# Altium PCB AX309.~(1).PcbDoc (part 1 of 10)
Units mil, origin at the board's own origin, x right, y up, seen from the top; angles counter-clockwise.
Board outline 5185 x 3614 mil, 4 copper layers (Top Layer, GND, Mid-Layer 1, Bottom Layer); 191 components, 352 nets, 1106 pads, 425 vias.
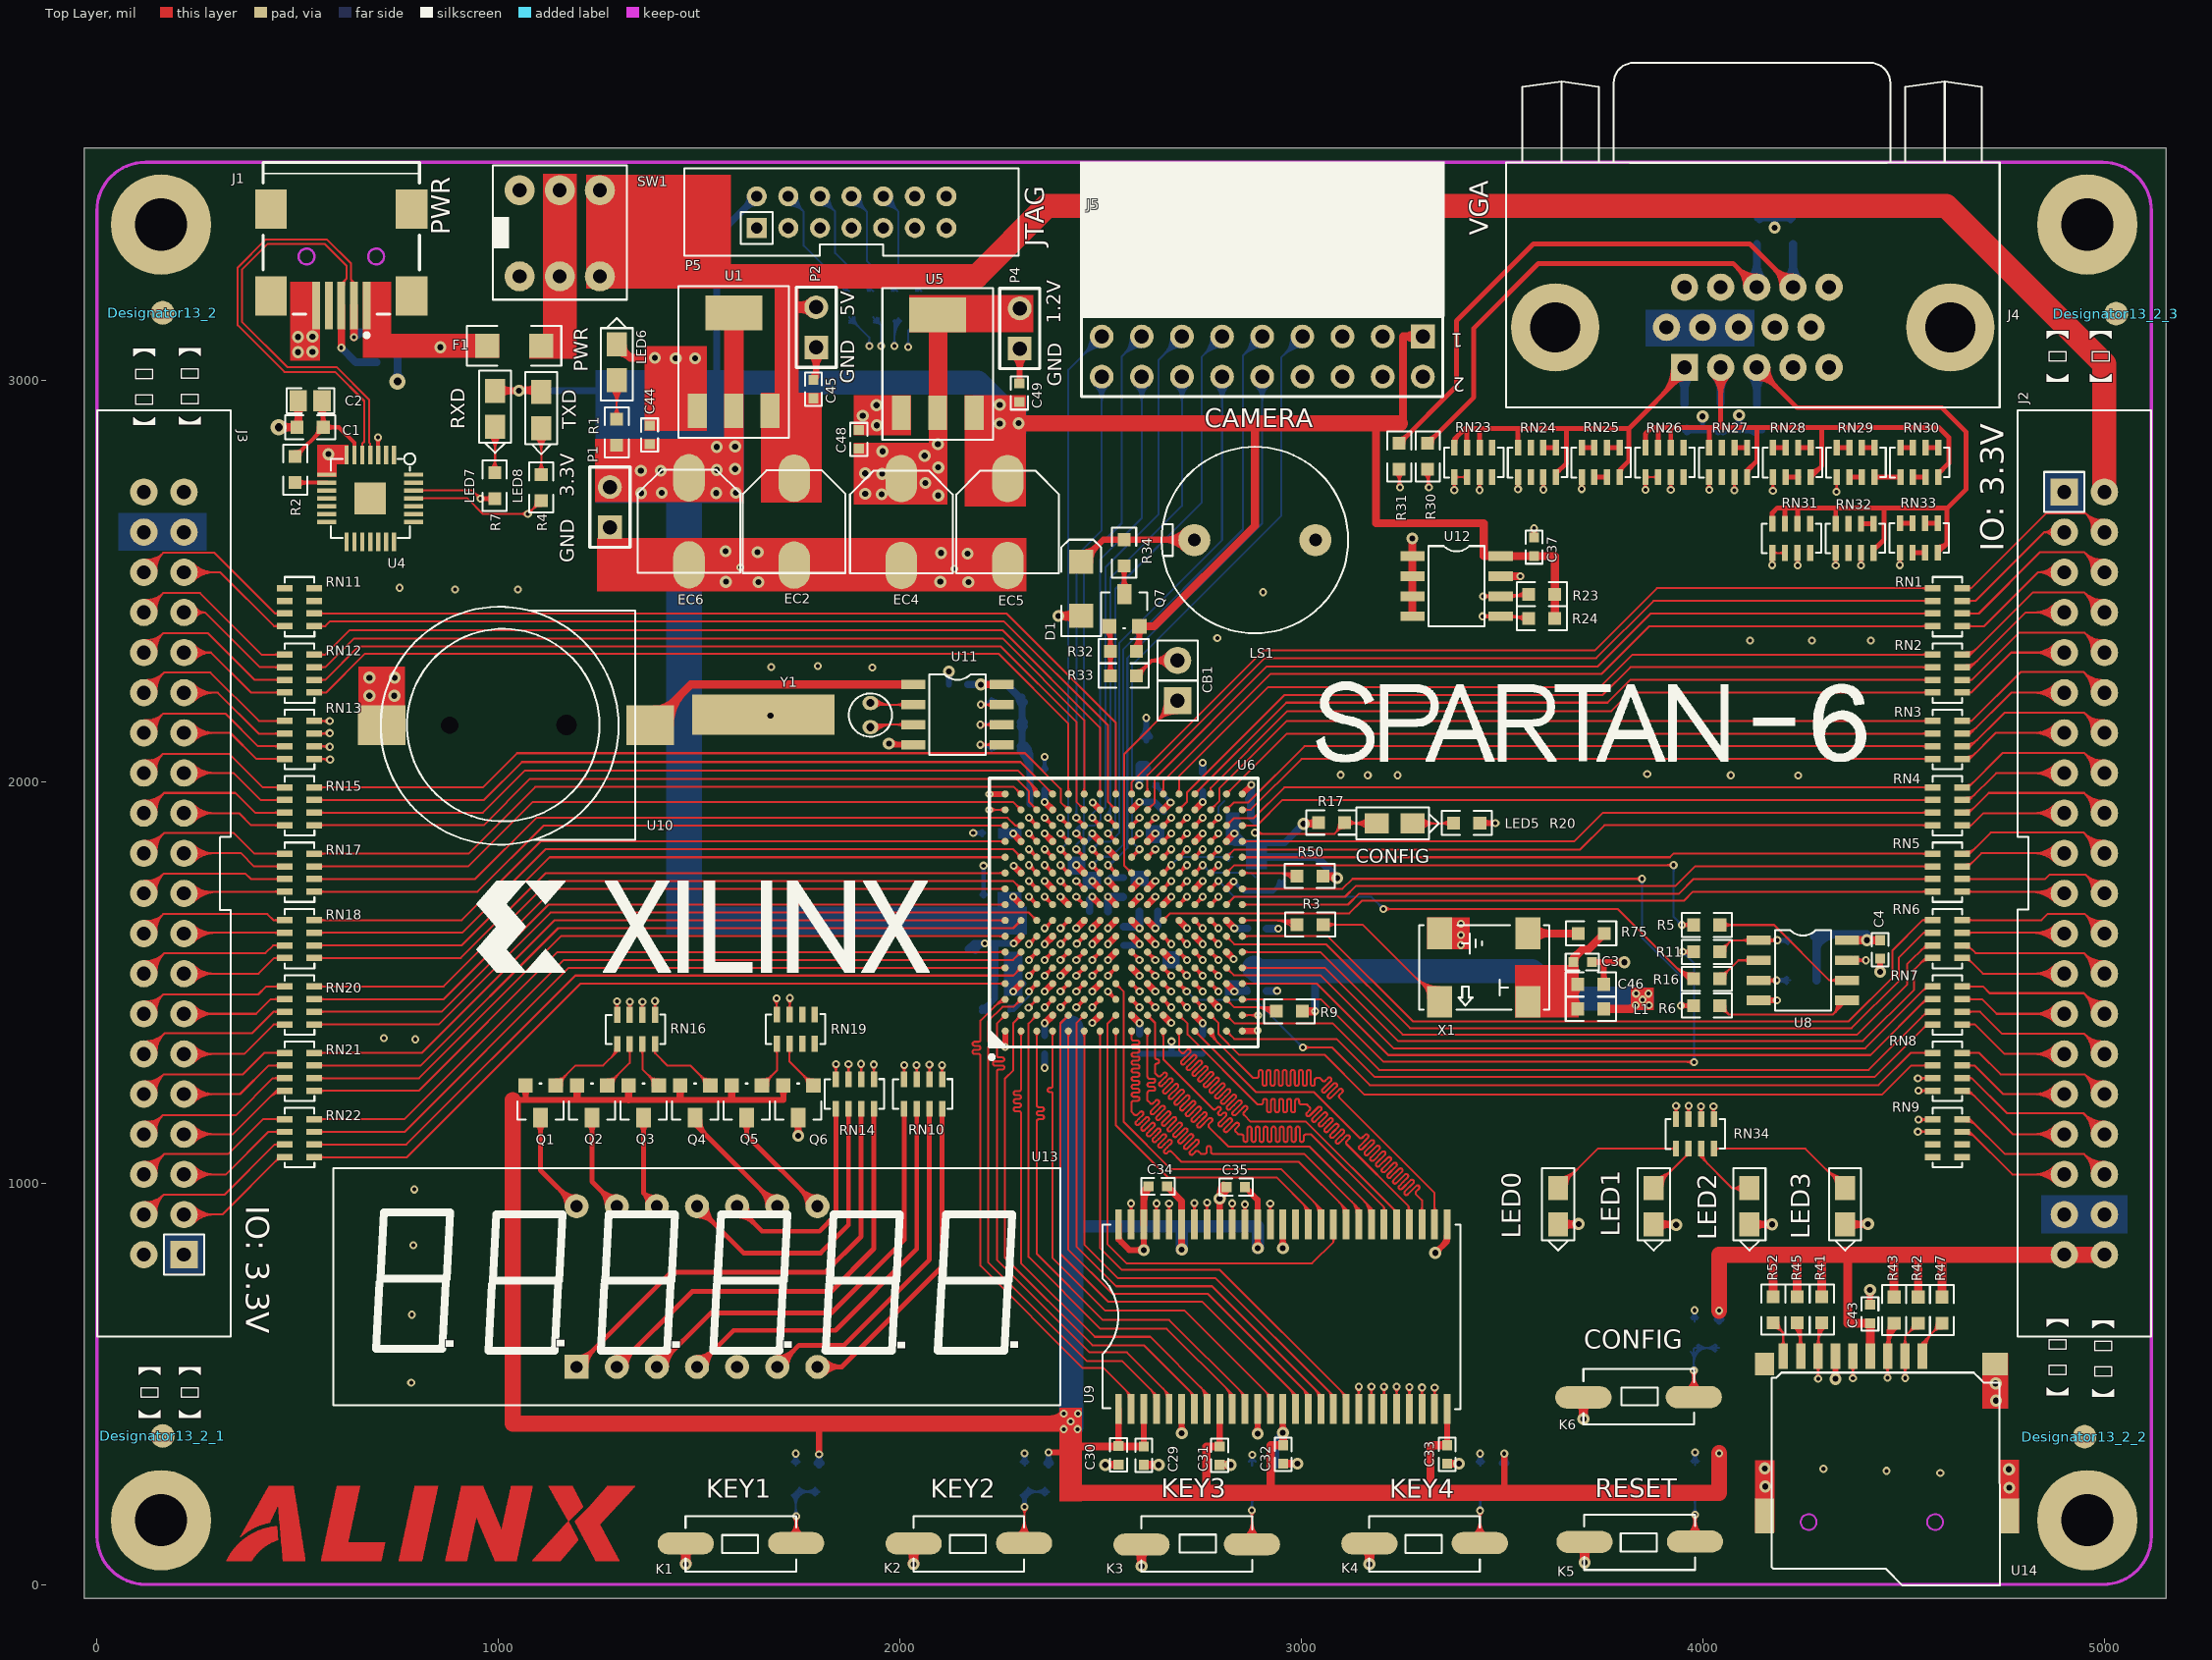
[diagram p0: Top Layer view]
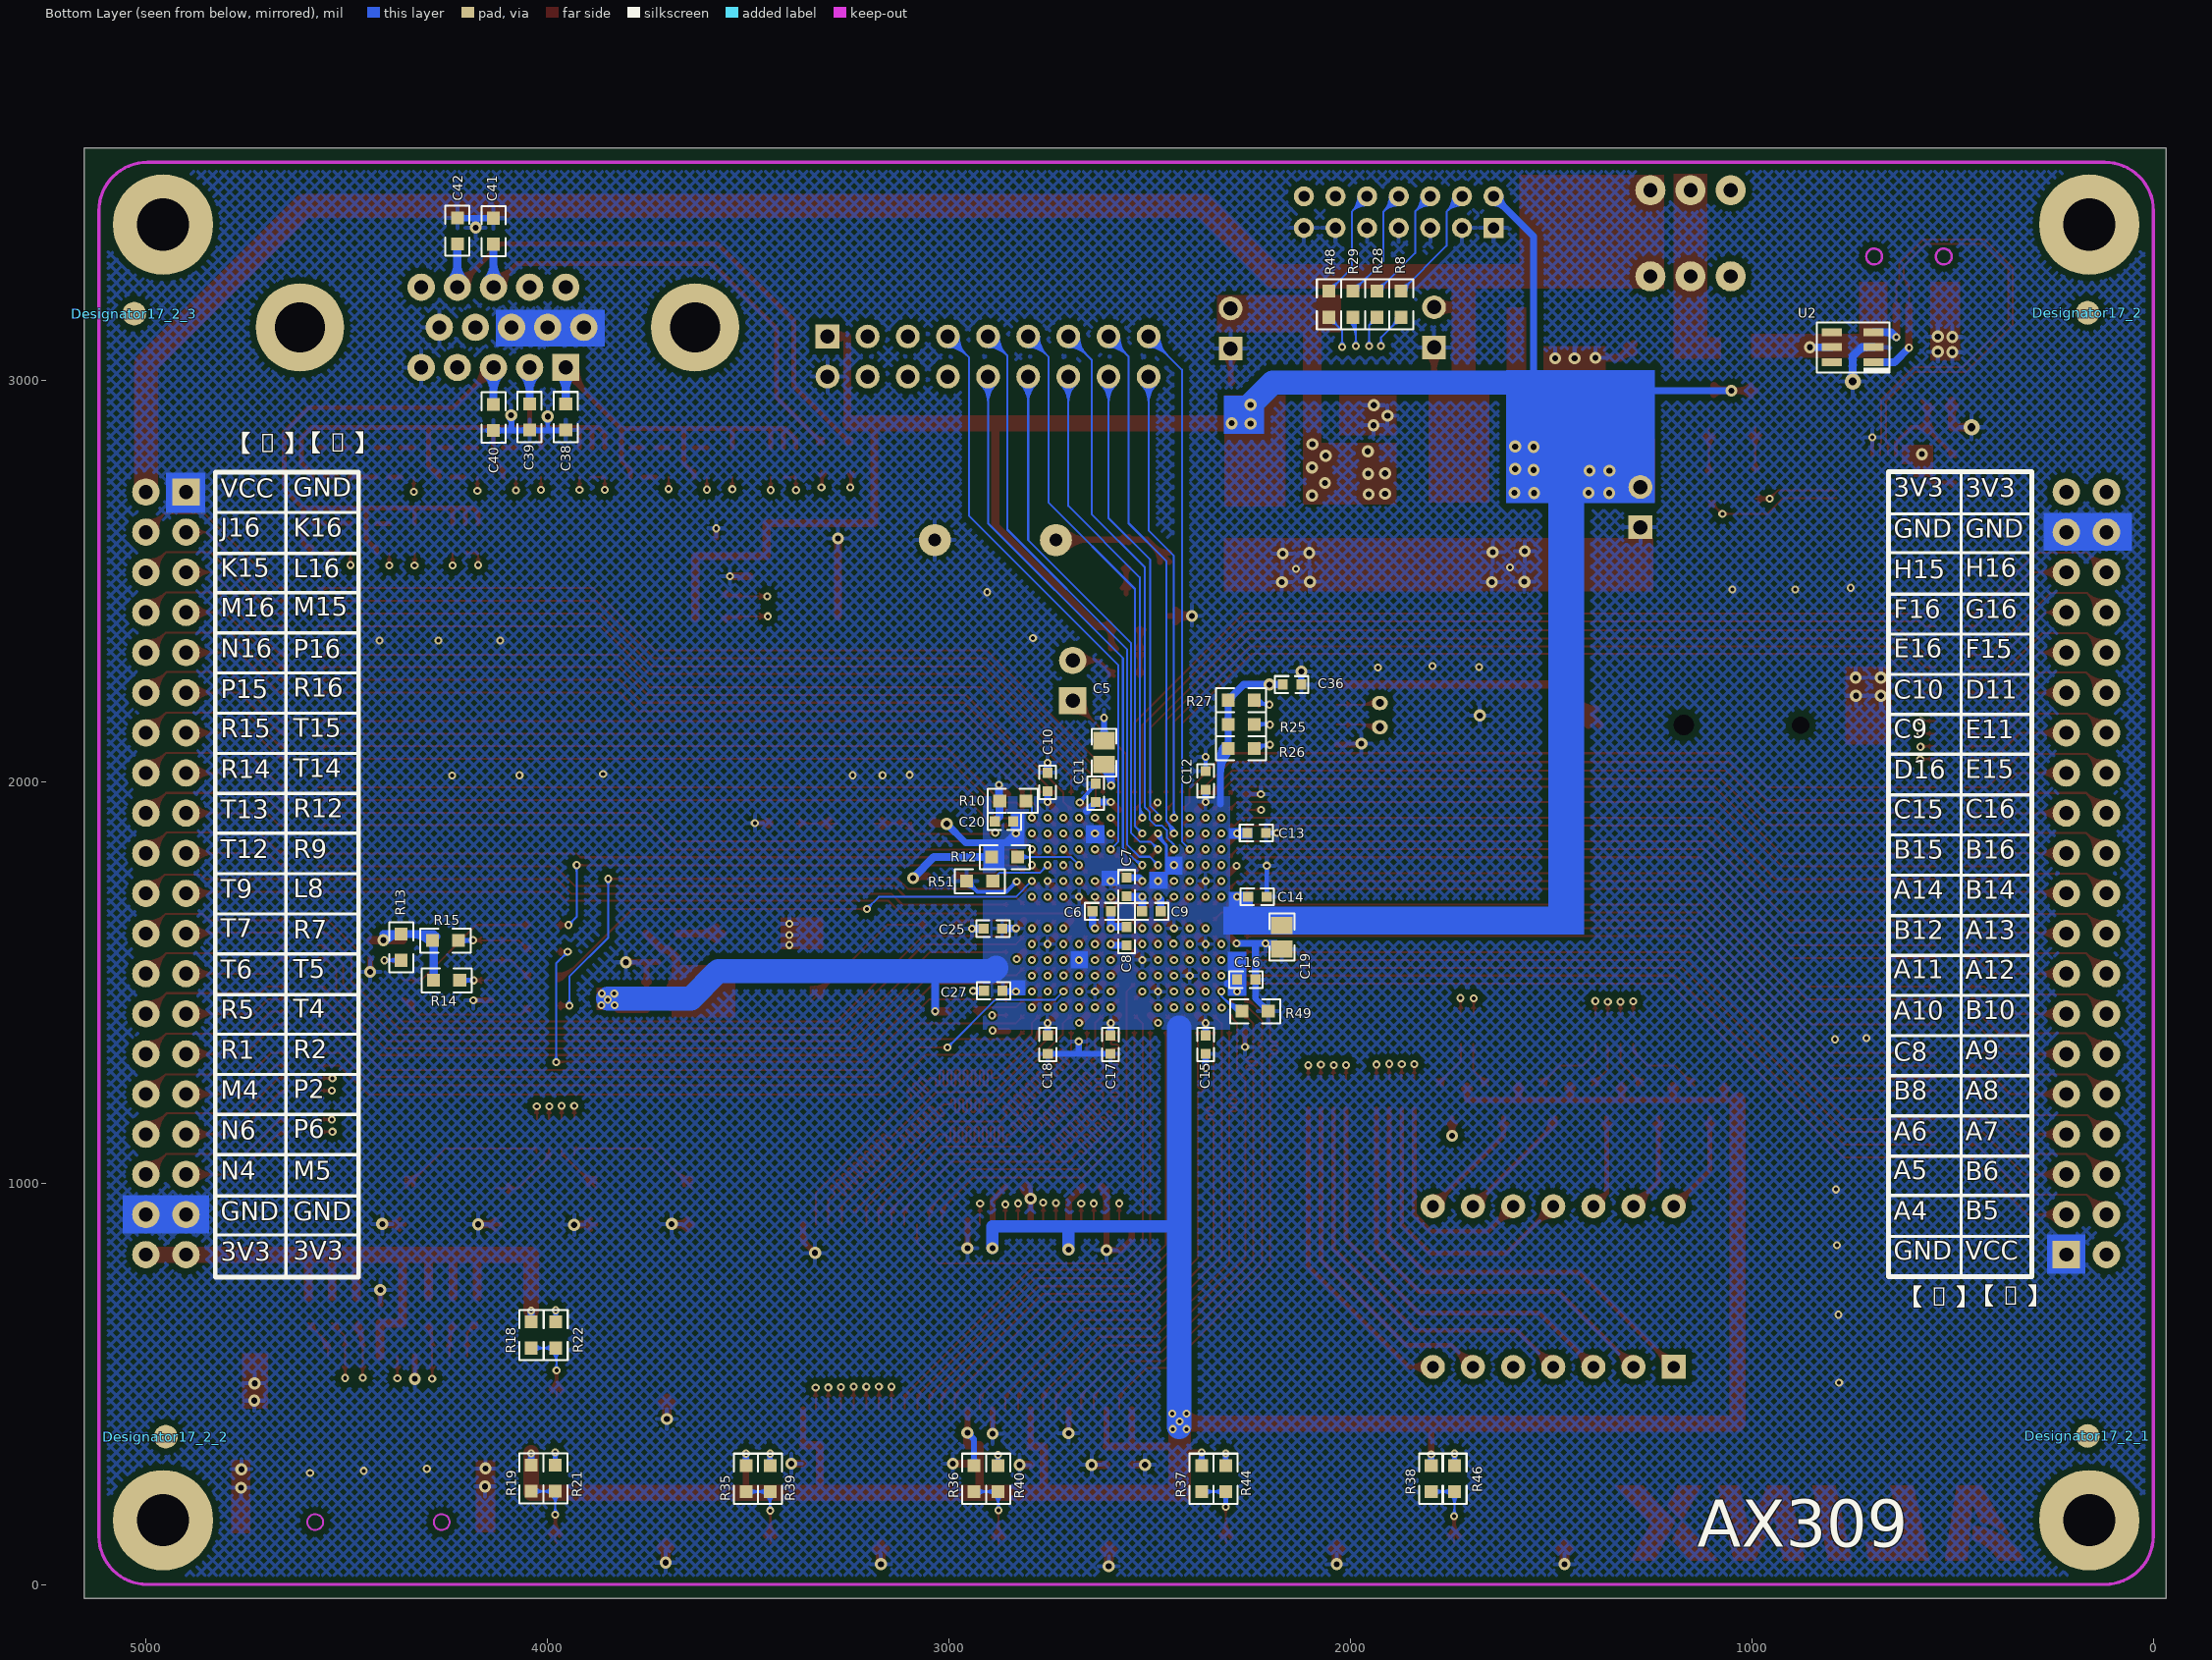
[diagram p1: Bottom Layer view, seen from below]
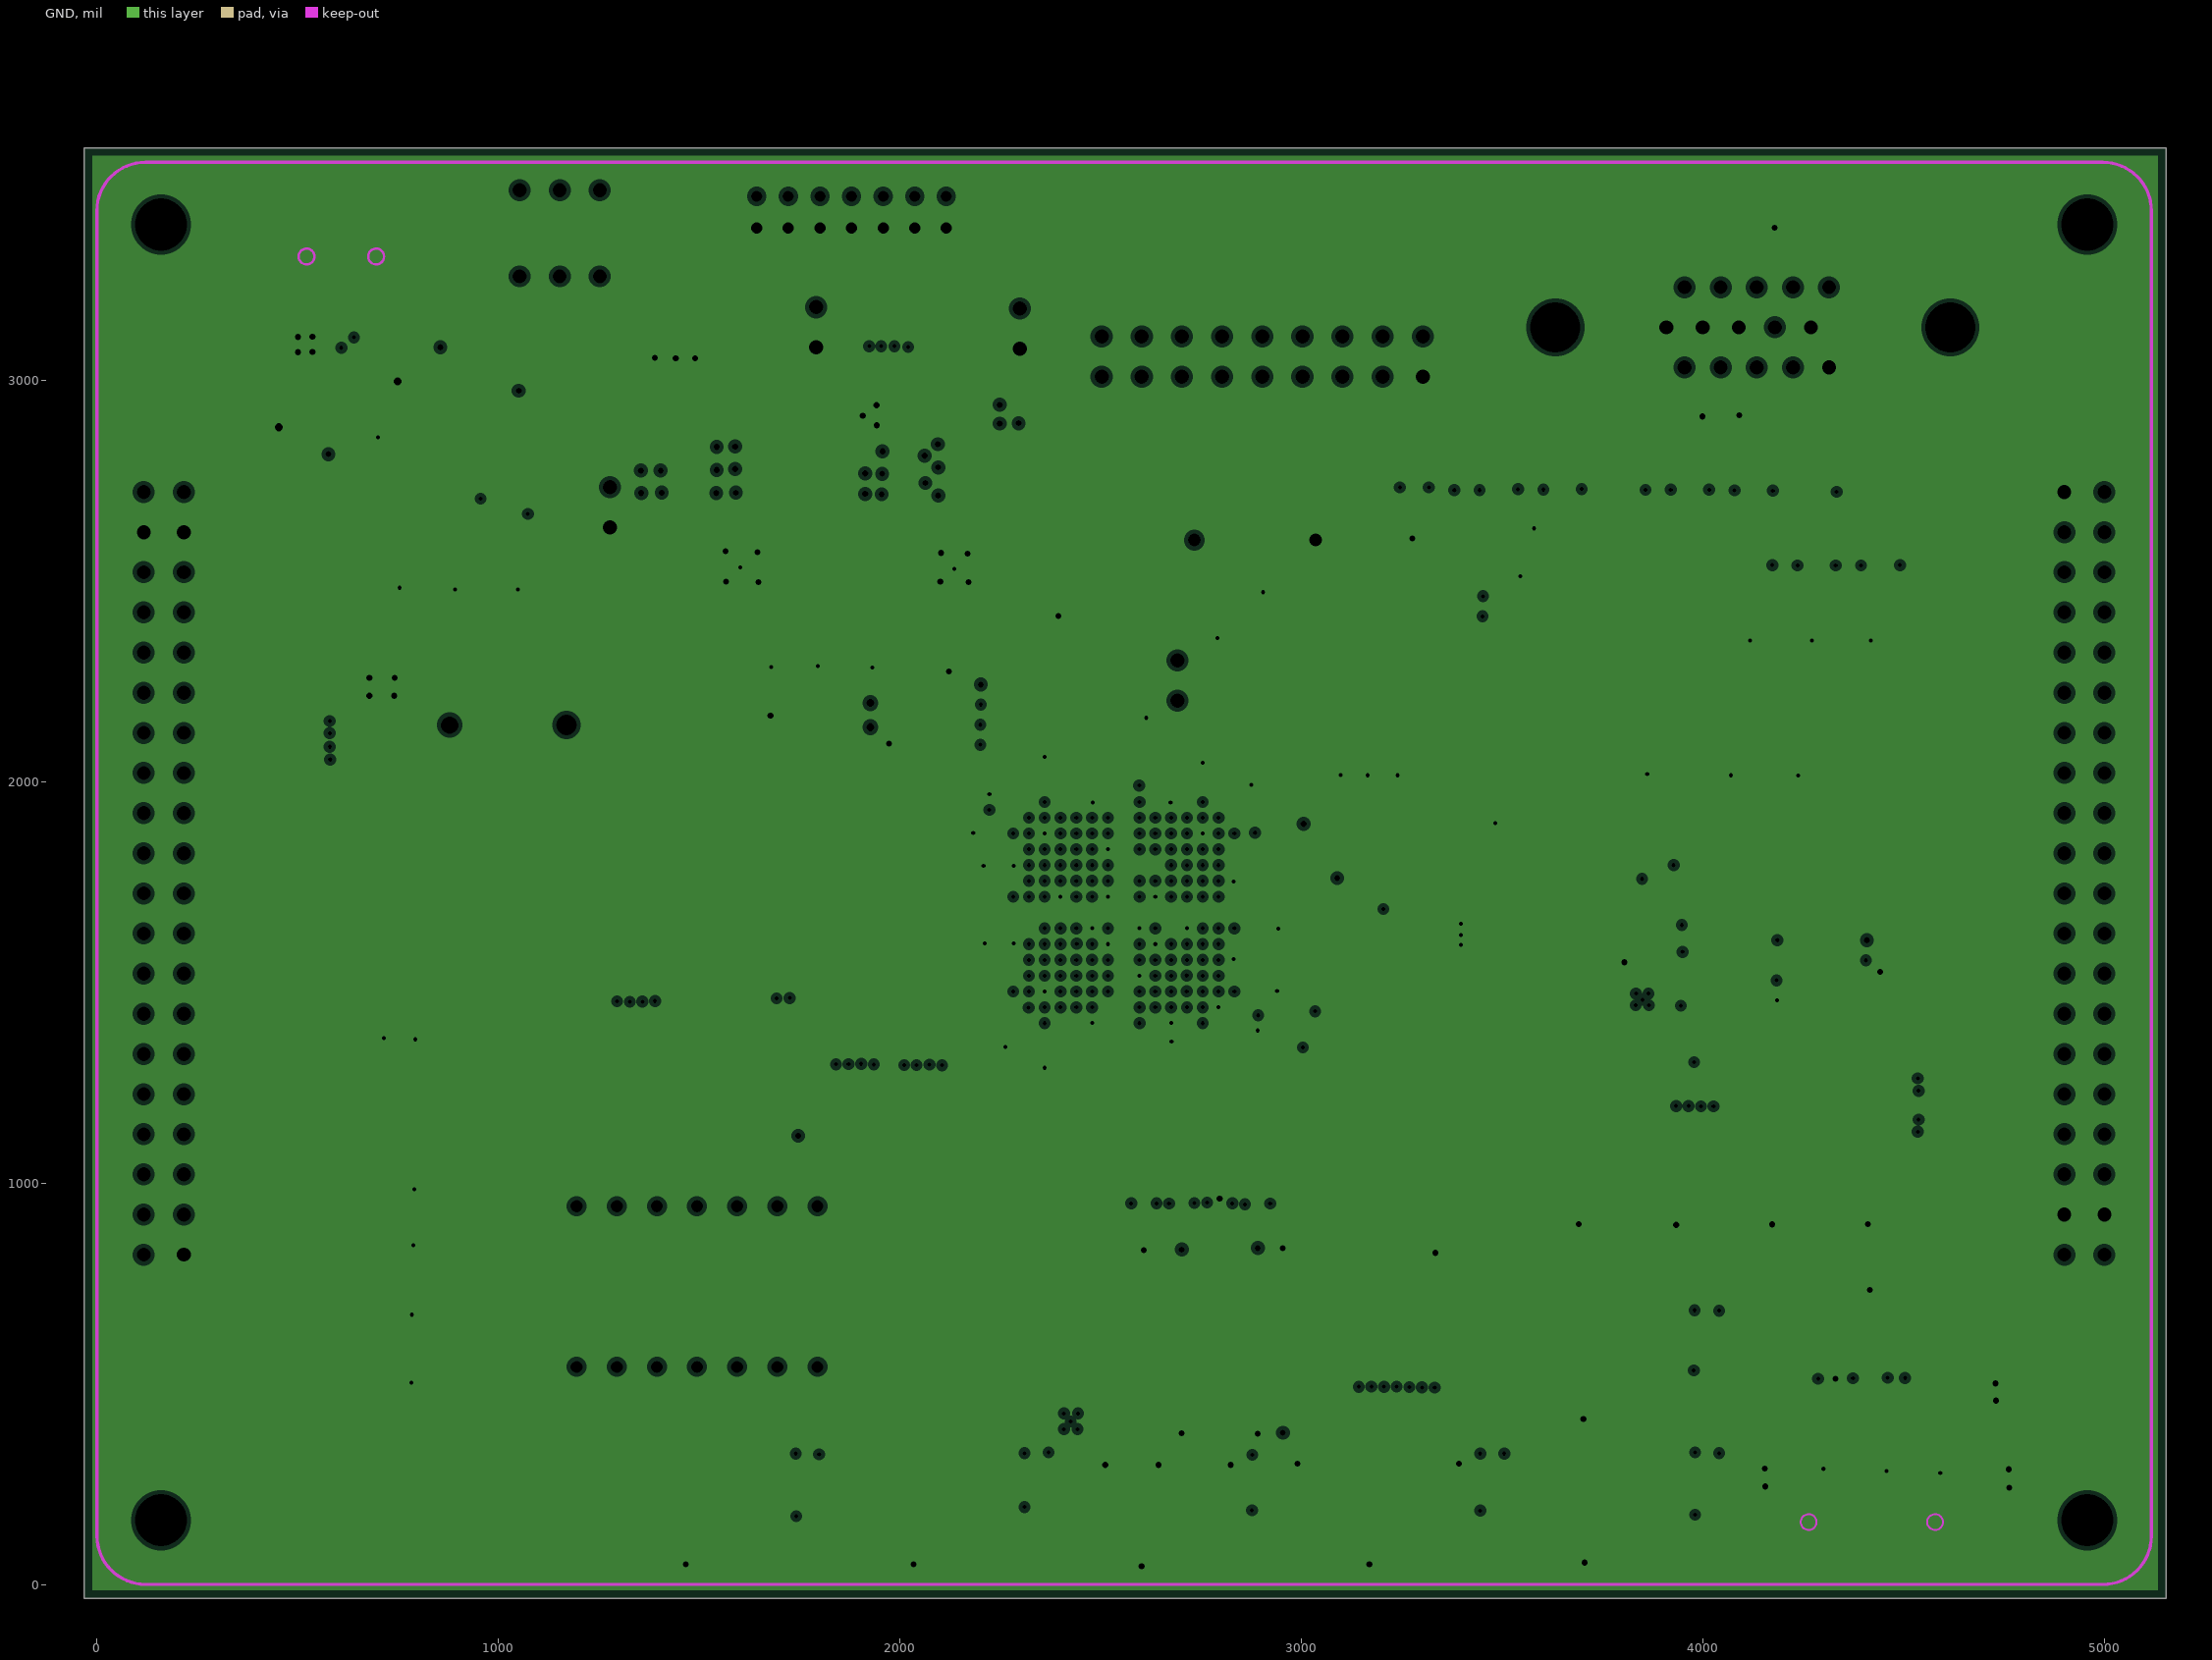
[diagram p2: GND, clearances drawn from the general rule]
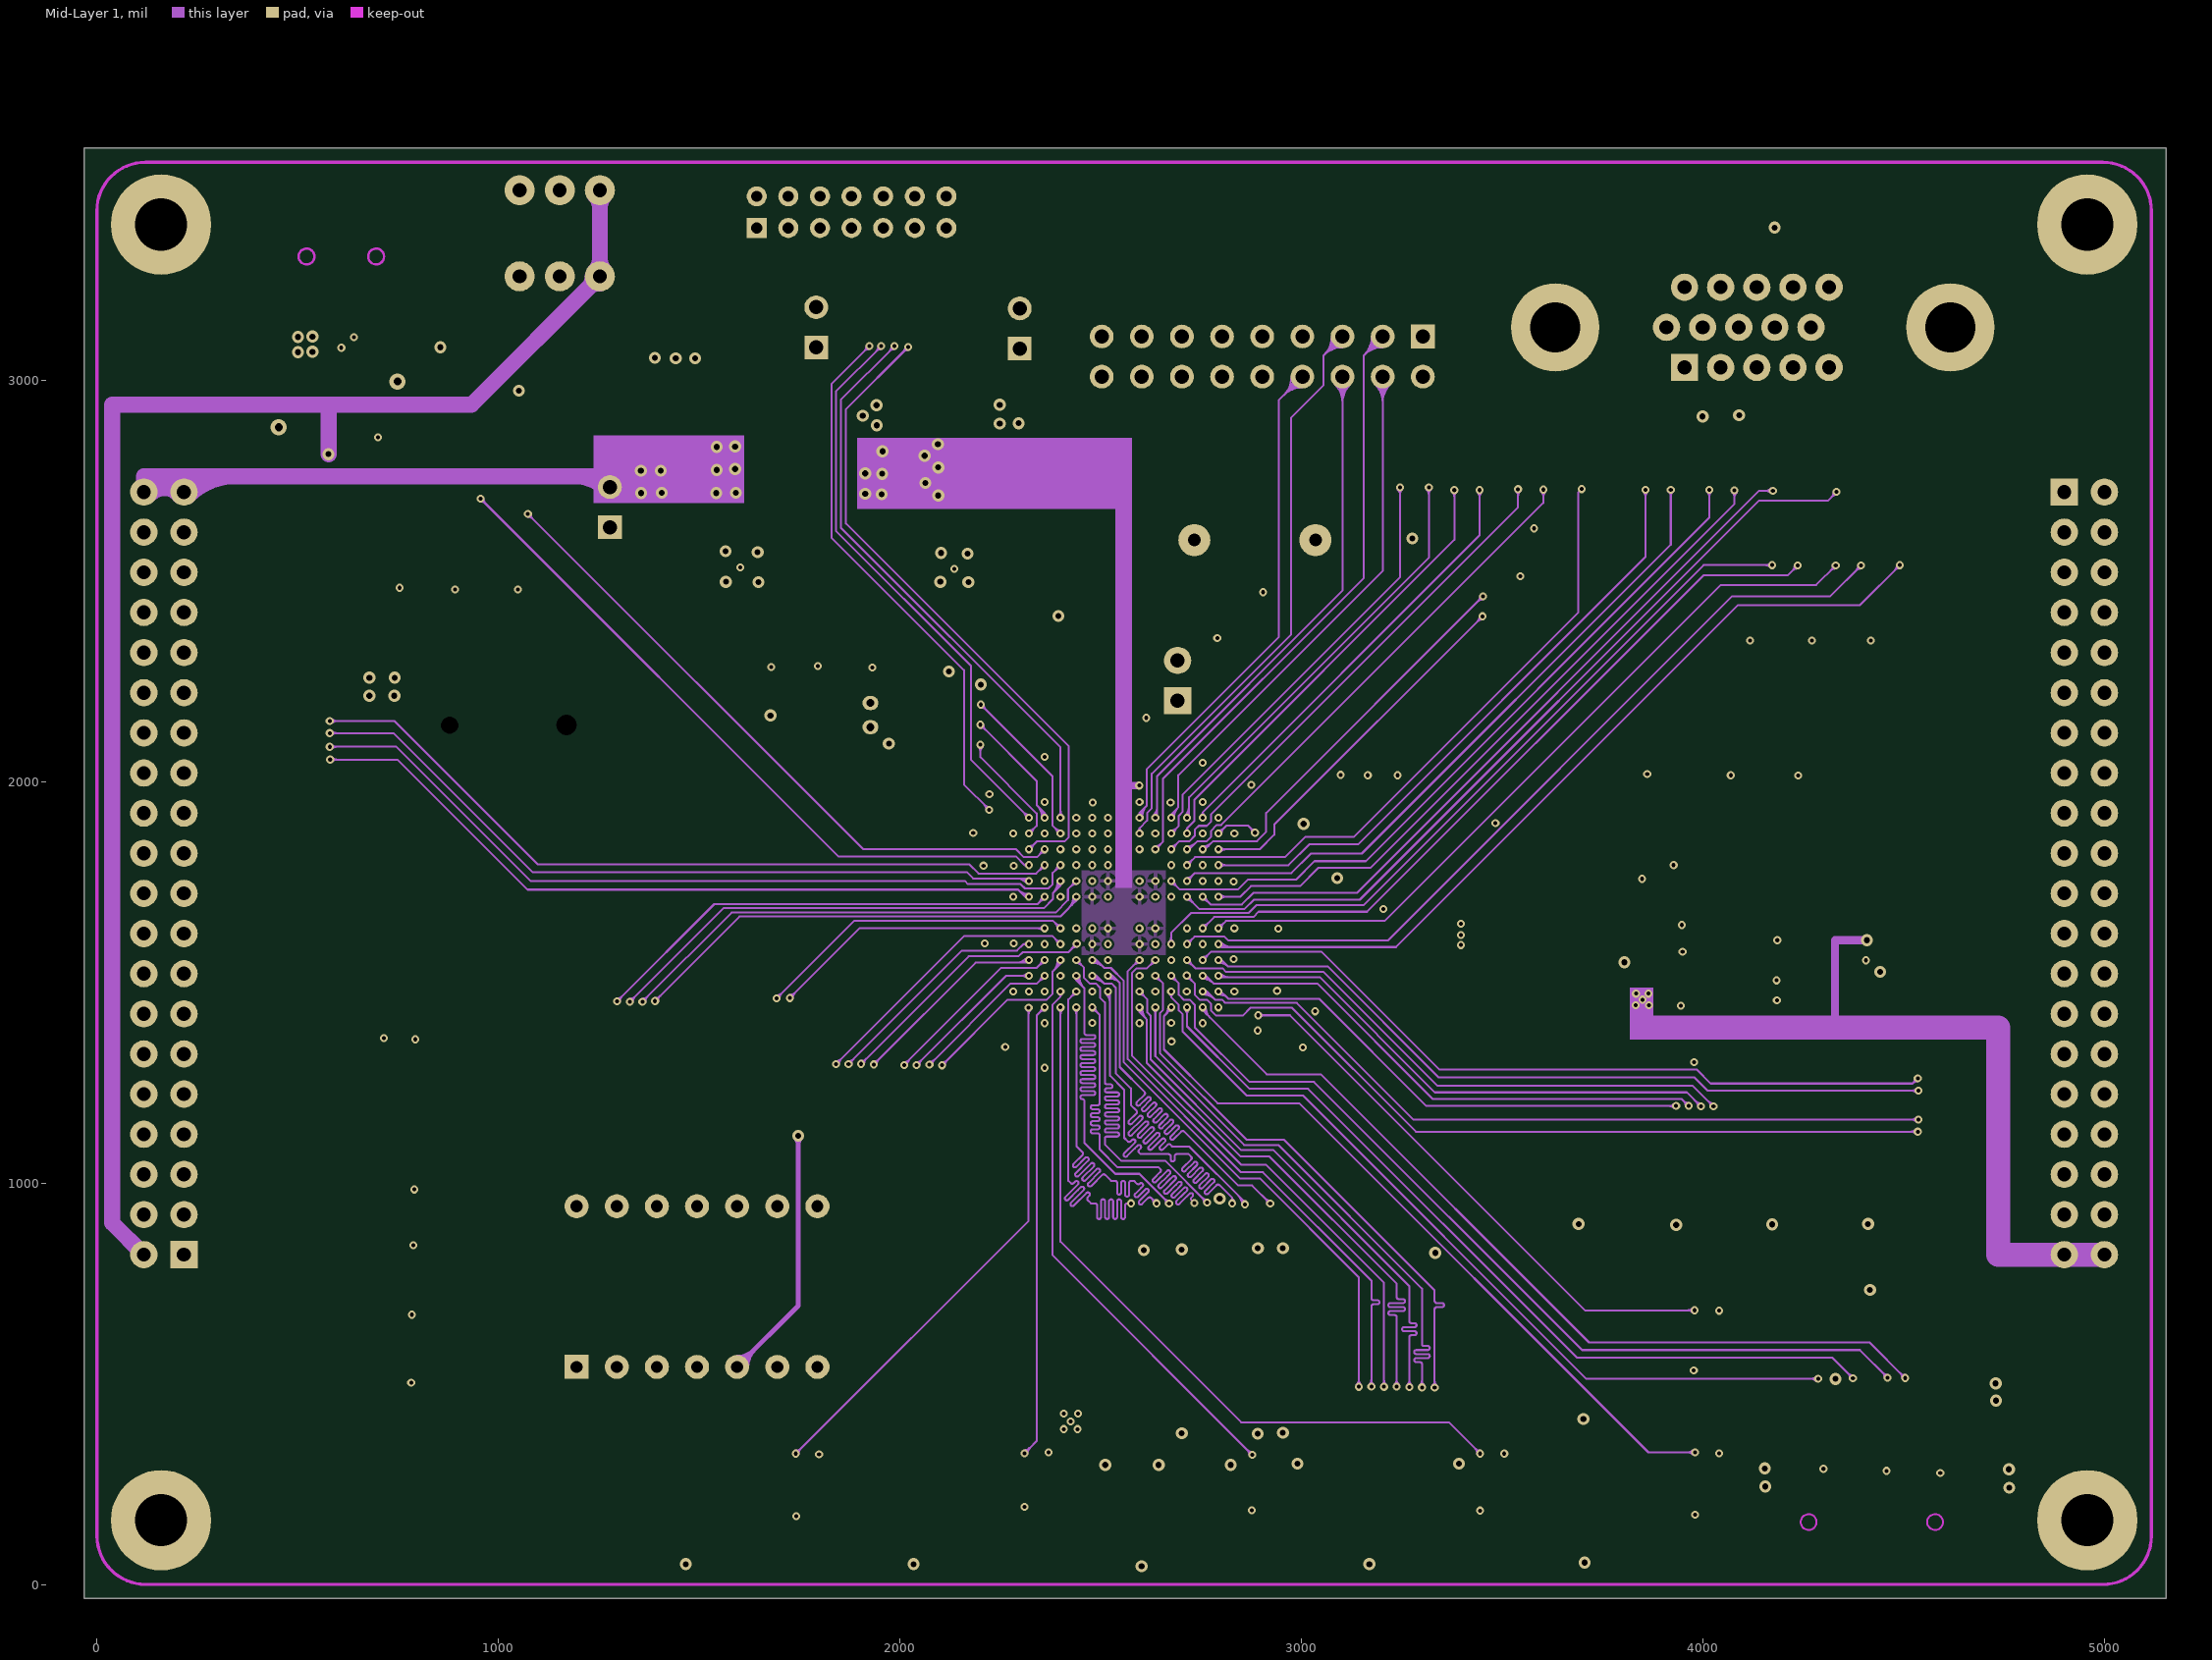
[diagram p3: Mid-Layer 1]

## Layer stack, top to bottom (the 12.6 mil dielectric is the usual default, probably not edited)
Top Solder: solder mask 0.4, Solder Resist, Dk 3.5
Top Layer: signal copper 1.4
Dielectric1: core 12.6, FR-4, Dk 4.8
GND: plane copper 1.4, net GND
Dielectric3: prepreg 12.6, FR-4, Dk 4.8
Mid-Layer 1: signal copper 1.4
Dielectric2: core 12.6, FR-4, Dk 4.8
Bottom Layer: signal copper 1.4
Bottom Solder: solder mask 0.4, Solder Resist, Dk 3.5

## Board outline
-31,3579.3 5154,3579.3 5154,3242.3 5154,-34.7 4892,-34.7 -31,-34.7 -31,3579.3

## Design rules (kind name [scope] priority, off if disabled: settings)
Clearance [All] p1: gap=5
ComponentClearance [All] p1 off: gap=10 collisioncheckmode=3 verticalgap=10 showdistances=FALSE
FanoutControl [InNet('GND')] p1: bgadir=Out bgaviamode=Centered fanoutstyle=Auto fanoutdirection=Alternating viagrid=1
FanoutControl Fanout_BGA [IsBGA] p2: bgadir=Out bgaviamode=Centered fanoutstyle=Auto fanoutdirection=Alternating viagrid=1 // Fanout_BGA (Default Rule)
FanoutControl Fanout_LCC [IsLCC] p3: bgadir=Out bgaviamode=Centered fanoutstyle=Auto fanoutdirection=Alternating viagrid=1 // Fanout_LCC (Default Rule)
FanoutControl Fanout_SOIC [IsSOIC] p4: bgadir=Out bgaviamode=Centered fanoutstyle=Auto fanoutdirection=Alternating viagrid=1 // Fanout_SOIC (Default Rule)
FanoutControl Fanout_Small [(CompPinCount < 5)] p5: bgadir=Out bgaviamode=Centered fanoutstyle=Auto fanoutdirection=OutThenIn viagrid=1 // Fanout_Small (Default Rule)
FanoutControl Fanout_Default [All] p6: bgadir=Out bgaviamode=Centered fanoutstyle=Auto fanoutdirection=Alternating viagrid=1 // Fanout_Default (Default Rule)
HoleSize [All] p1: absolutevalues=TRUE maxlimit=200 minlimit=1 maxpercent=80.000 minpercent=20.000
HoleToHoleClearance [All] p1 off: gap=10 allowstackedmicrovias=TRUE
LayerPairs [All] p1 off: enforce=TRUE
MatchedLengths SDRAM_DB [InNetClass('S_DB[0..15]')] p1: tolerance=50 checknetsindiffpair=TRUE checkdiffpairvsdiffpair=TRUE checkothers=TRUE
MatchedLengths SDRAM_A [InNetClass('S_A[0..12]')] p2: tolerance=50 checknetsindiffpair=TRUE checkdiffpairvsdiffpair=TRUE checkothers=TRUE
MinimumSolderMaskSliver [All] p1 off: minsoldermaskwidth=10
NetAntennae [All] p1 off: netantennaetolerance=0
PlaneClearance [All] p1: clearance=10
PlaneConnect [All] p1: planeconnectstyle=Relief reliefexpansion=6 reliefentries=4 reliefconductorwidth=5 reliefairgap=6
PolygonConnect [All] p1: connectstyle=Relief reliefconductorwidth=10 reliefentries=4 polygonreliefangle="90 Angle" airgapwidth=10
RoutingVias [All] p1: holewidth=10 width=20 viastyle="Through Hole" minholewidth=10 minwidth=20 maxholewidth=50 maxwidth=100
SilkToSilkClearance [All] p1 off: silktosilkclearance=10
SilkToSolderMaskClearance SilkscreenOverComponentPads [IsPad] p1 off: minsilkscreentomaskgap=10 clearancetoexposedcopper=TRUE
SolderMaskExpansion [All] p1: expansion=4
Width D2V5 [InNet('D2V5')] p1: maxlimit=60 minlimit=15 preferedwidth=20
Width D1V2 [InNet('D1V2')] p2: maxlimit=60 minlimit=15 preferedwidth=20
Width D3V3 [InNet('D3V3')] p3: maxlimit=60 minlimit=6 preferedwidth=20
Width GND [InNet('GND')] p4 off: maxlimit=60 minlimit=10 preferedwidth=20
Width [All] p5 off: maxlimit=60 minlimit=5 preferedwidth=6
14 further rules are at their usual default settings.

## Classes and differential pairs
net class S_DB[0..15]: S_DB0 S_DB1 S_DB2 S_DB3 S_DB4 S_DB5 S_DB6 S_DB7 S_DB8 S_DB9 S_DB10 S_DB11 S_DB12 S_DB13 S_DB14 S_DB15
net class S_A[0..12]: S_A0 S_A1 S_A2 S_A3 S_A4 S_A5 S_A6 S_A7 S_A8 S_A9 S_A10 S_A11 S_A12
component class 1_POWER: C1 C2 C44 C45 C48 C49 EC2 EC4 EC5 EC6 F1 J1 LED6 LED7 LED8 P1 P2 P4 R1 R2 R4 R7 SW1 U1 U2 U4 U5
component class 5_SDRAM: C29 C30 C31 C32 C33 C34 C35 U9
component class 4_FPGA: C3 C4 C5 C6 C7 C8 C9 C10 C11 C12 C13 C14 C15 C16 C17 C18 C19 C20 C25 C27 C46 K5 K6 L1 LED5 P5 R3 R8 R10 R12 R13 R14 R15 R16 R17 R18 R19 R20 R21 R22 R28 R29 R48 R75 U8 X1
component class 3_FPGA: R5 R6 R9 R11 R50 R51
component class 6_DIG: C36 C37 J2 J3 LED0 LED1 LED2 LED3 Q1 Q2 Q3 Q4 Q5 Q6 R23 R24 R25 R26 R27 RN1 RN2 RN3 RN4 RN5 RN6 RN7 RN8 RN9 RN10 RN11 RN12 RN13 RN14 RN15 RN16 RN17 RN18 RN19 RN20 RN21 RN22 RN34 U10 U11 U12 U13 Y1
component class 7_VGA: C38 C39 C40 C41 C42 C43 CB1 D1 J4 J5 K1 K2 K3 K4 LS1 Q7 R30 R31 R32 R33 R34 R35 R36 R37 R38 R39 R40 R41 R42 R43 R44 R45 R46 R47 R52 RN23 RN24 RN25 RN26 RN27 RN28 RN29 RN30 RN31 RN32 RN33 U14
net class DIG[0..7]: DIG0 DIG1 DIG2 DIG3 DIG4 DIG5 DIG6 DIG7
net class SEL[0..5]: SEL0 SEL1 SEL2 SEL3 SEL4 SEL5
net class VGAD[15..0]: VGAD0 VGAD1 VGAD2 VGAD3 VGAD4 VGAD5 VGAD6 VGAD7 VGAD8 VGAD9 VGAD10 VGAD11 VGAD12 VGAD13 VGAD14 VGAD15
component class 2_FPGA: R49 U6

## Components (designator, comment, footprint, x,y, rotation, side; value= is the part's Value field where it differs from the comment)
C1 "1uF" 0603 564,2883 r180 top
C2 "10uF" 0805 561,2949 r180 top
C3 "0.1uF" 0402 3678,1551 r0 top
C4 "104" 0402 4442,1559 r90 top
C5 "10uF" 0805 2614,2043 r90 bottom
C6 "104" 0402 2473,1677 r0 bottom
C7 "104" 0402 2558,1592 r90 bottom
C8 "104" 0402 2558,1761 r270 bottom
C9 "104" 0402 2643,1677 r180 bottom
C10 "104" 0402 2755,1976 r90 bottom
C11 "104" 0402 2635,1949 r90 bottom
C12 "104" 0402 2361,1980 r90 bottom
C13 "104" 0402 2257,1872 r180 bottom
C14 "104" 0402 2255,1713 r180 bottom
C15 "104" 0402 2361.15,1368 r270 bottom
C16 "104" 0402 2283,1507 r180 bottom
C17 "104" 0402 2598,1368 r270 bottom
C18 "104" 0402 2754,1368 r270 bottom
C19 "10uF" 0805 2171,1642 r270 bottom
C20 "104" 0402 2840,1901 r0 bottom
C25 "104" 0402 2868,1634 r0 bottom
C27 "104" 0402 2867,1479 r0 bottom
C29 "104" 0402 2607.99,344.01 r270 top
C30 "104" 0402 2545,345 r270 top
C31 "104" 0402 2797,344 r270 top
C32 "104" 0402 2955,347 r270 top
C33 "104" 0402 3364,347 r270 top
C34 "104" 0402 2666,992 r180 top
C35 "104" 0402 2860,990 r180 top
C36 "104" 0402 2169,2242 r180 bottom
C37 "104" 0402 3580,2562 r90 top
C38 "5p1" 0603 3955,2941 r270 bottom
C39 "5p1" 0603 4045,2941 r270 bottom
C40 "5p1" 0603 4135,2940 r270 bottom
C41 "5p1" 0603 4135,3339 r90 bottom
C42 "5p1" 0603 4225,3340 r90 bottom
C43 "104" 0402 4417,651 r90 top
C44 "104" 0402 1377,2841 r90 top
C45 "104" 0402 1785,2955 r90 top
C46 "4.7uF" 0603 3689,1495 r0 top
C48 "104" 0402 1898,2830 r90 top
C49 "104" 0402 2298,2946 r90 top
CB1 "BUZ" SIP2 2692,2202 r90 top
D1 "4148" 1206A 2452,2413 r90 top
Designator13_2 "Comment" TPS 164,3168 r0 top
Designator13_2_1 "Comment" TPS 164,370 r0 top
Designator13_2_2 "Comment" TPS 4951.33,368 r0 top
Designator13_2_3 "Comment" TPS 5030,3166 r0 top
Designator17_2 "Comment" TPS 164,3168 r180 bottom
Designator17_2_1 "Comment" TPS 164,370 r180 bottom
Designator17_2_2 "Comment" TPS 4951.33,368 r180 bottom
Designator17_2_3 "Comment" TPS 5030,3166 r180 bottom
EC2 "100uF/16V" AEC6.5 1737,2756 r270 top
EC4 "100uF/16V" AEC6.5 2004,2755 r270 top
EC5 "100uF/16V" AEC6.5 2269,2755 r270 top
EC6 "100uF/16V" AEC6.5 1475,2757 r270 top
F1 "Fuse" 1206 972,3086 r0 top
J1 "EC2" MINIUSBB 609,3186.3 r270 top
J2 "IDC40" IDC-40J 4951,1771.65 r270 top
J3 "IDC40" IDC-40J 167,1771.65 r90 top
J4 "VGA" VGA 3955,3032 r90 top
J5 "Header 9X2" HDR2X9 3303,3109.17 r180 top locked
K1 "KEY1" KEY735SO 1742,103 r180 top
K2 "KEY2" KEY735SO 2309.67,103 r180 top
K3 "KEY3" KEY735SO 2602.33,99.2 r0 top
K4 "KEY4" KEY735SO 3445,103 r180 top
K5 "RESET" KEY735SO 3981,107 r180 top
K6 "CONFIG" KEY735SO 3703,466 r0 top
L1 "Bead" 0603 3754,1434 r180 top
LED0 "LED0" LEDSO 3640,897 r90 top
LED1 "LED1" LEDso 3878.33,897 r90 top
LED2 "LED2" LEDSO 4116.67,897 r90 top
LED3 "LED3" LEDSO 4355,897 r90 top
LED5 "CONFIG" LEDSO 3278,1896 r180 top
LED6 "D3V3" LEDSO 1295,3090 r270 top
LED7 "RXD" LEDSO 992,2884 r90 top
LED8 "TXD" LEDSO 1107,2881 r90 top
LS1 "BUZZER" BUZZER 2734,2602 r0 top
P1 "3.3V" HDR1X2 1278,2634 r90 top
P2 "5V" HDR1X2 1792,3082 r90 top
P4 "1.2V" HDR1X2 2299,3079 r90 top
P5 "JTAG" JTAG14-.5 1880,3419 r0 top
Q1 "9012" SOT23 1143,1243 r180 top
Q2 "9012" SOT23 1271.4,1243 r180 top
Q3 "9012" SOT23 1399.8,1243 r180 top
Q4 "9012" SOT23 1528.2,1243 r180 top
Q5 "9012" SOT23 1656.6,1243 r180 top
Q6 "9012" SOT23 1785,1243 r180 top
Q7 "9012" SOT23 2522,2387 r0 top
R1 "1K" 0603 1295,2838 r90 top
R2 "10k" 0603 494,2745 r90 top
R3 "33R" 0603 2990,1644 r0 top
R4 "1K" 0603 1107,2700.3 r90 top
R5 "33R" 0603 3978,1643 r0 top
R6 "33R" 0603 3978,1442 r0 top
R7 "1K" 0603 991,2705 r90 top
R8 "33" 0603 1874,3222 r270 bottom
R9 "10K" 0603 2938,1428 r0 top
R10 "10K" 0603 2874,1952 r180 bottom
R11 "33R" 0603 3978,1576 r0 top
R12 "10K" 0603 2894,1812 r180 bottom
R13 "10K" 0603 4365,1555 r90 bottom
R14 "10K" 0603 4219,1505 r0 bottom
R15 "10K" 0603 4222,1604 r0 bottom
R16 "33R" 0603 3978,1509 r0 top
R17 "330" 0603 3108,1898 r180 top
R18 "10k" 0603 4041,654 r270 bottom
R19 "10k" 0603 4041,297 r270 bottom
R20 "220" 0603 3445,1897 r180 top
R21 "100" 0603 3981,297 r270 bottom
R22 "100" 0603 3980,654 r270 bottom
R23 "4k7" 0603 3632,2467 r180 top
R24 "4k7" 0603 3632,2407 r180 top
R25 "10k" 0603 2305,2143 r180 bottom
R26 "10k" 0603 2305,2083 r180 bottom
R27 "10k" 0603 2305,2203 r180 bottom
R28 "33" 0603 1934,3222 r270 bottom
R29 "33" 0603 1994,3222 r270 bottom
R30 "22" 0603 3315,2843 r270 top
R31 "22" 0603 3244,2843 r270 top
R32 "1K" 0603 2590,2325 r180 top
R33 "2K2" 0603 2590,2264 r180 top
R34 "15" 0603 2559,2538 r90 top
R35 "10k" 0603 3506,296 r270 bottom
R36 "10k" 0603 2938,296 r270 bottom
R37 "10k" 0603 2371,296 r270 bottom
R38 "10k" 0603 1799,296 r270 bottom
R39 "100" 0603 3446,296 r270 bottom
R40 "100" 0603 2878,296 r270 bottom
R41 "1K" 0603 4297,717 r270 top
R42 "1K" 0603 4537,716 r270 top
R43 "1K" 0603 4477,716 r270 top
R44 "100" 0603 2311,296 r270 bottom
R45 "1K" 0603 4236,717 r270 top
R46 "100" 0603 1741,296 r270 bottom
R47 "1K" 0603 4596,716 r270 top
R48 "33" 0603 2054,3222 r270 bottom
R49 "4K7" 0603 2270,1428 r180 bottom
R50 "1K" 0603 2989,1765 r0 top
R51 "1K" 0603 2891,1752 r0 bottom
R52 "1K" 0603 4176,717 r270 top
R75 "10k" 0603 3690,1622 r0 top
RN1 "33R" RN-8P 4573,2482 r0 top
RN2 "33R" RN-8P 4573,2316.62 r0 top
RN3 "33R" RN-8P 4573,2151.25 r0 top
RN4 "33R" RN-8P 4573,1985.88 r0 top
RN5 "33R" RN-8P 4573,1820.5 r0 top
RN6 "33R" RN-8P 4573,1655.12 r0 top
RN7 "33R" RN-8P 4573,1489.75 r0 top
RN8 "33R" RN-8P 4573,1324.38 r0 top
RN9 "33R" RN-8P 4573,1159 r0 top
RN10 "470" RN-8P 2011,1185 r90 top
RN11 "33R" RN-8P 468,2482 r0 top
RN12 "33R" RN-8P 468,2316.62 r0 top
RN13 "33R" RN-8P 468,2151.25 r0 top
RN14 "470" RN-8P 1841,1185 r90 top
RN15 "33R" RN-8P 468,1985.88 r0 top
RN16 "470" RN-8P 1296,1346 r90 top
RN17 "33R" RN-8P 468,1820.5 r0 top
RN18 "33R" RN-8P 468,1655.12 r0 top
RN19 "470" RN-8P 1694,1347 r90 top
RN20 "33R" RN-8P 468,1489.75 r0 top
RN21 "33R" RN-8P 468,1324.38 r0 top
RN22 "33R" RN-8P 468,1159 r0 top
RN23 "1K" RN-8P 3476,2832 r270 top
RN24 "2K" RN-8P 3634.71,2832 r270 top
RN25 "2K" RN-8P 3793.43,2832 r270 top
RN26 "1K" RN-8P 3952.14,2832 r270 top
RN27 "2K" RN-8P 4110.86,2832 r270 top
RN28 "2K" RN-8P 4269.57,2832 r270 top
RN29 "2K" RN-8P 4428.29,2832 r270 top
RN30 "2K" RN-8P 4587,2832 r270 top
RN31 "1K" RN-8P 4268,2643 r270 top
RN32 "2K" RN-8P 4426,2643 r270 top
RN33 "2K" RN-8P 4586,2644 r270 top
RN34 "470" RN-8P 4028,1159 r270 top
SW1 "SW" KEY_DPDT 1053,3259 r90 top
U1 "1117-3.3" SOT223 1496,2924 r0 top
U2 "SRV05-4" SOT23-6 697,3045 r90 bottom
U4 "CP2102" QFN28 740,2814 r270 top
U5 "1117-1.2" SOT223 2004,2919 r0 top
U6 "XC6SLX9-2FTG256C" FTG256 2558,1674 r90 top locked
U8 "M25P16-VMN3PB" SO8 4140,1605 r0 top
U9 "HY57V2562GTR" TSOP-54 2545,437 r180 top
U10 "battery" BATSO 1418,2141 r0 top
U11 "DS1302" SO8 2034,2242 r0 top
U12 "24LC04" SO8 3277,2562 r0 top
U13 "HEX6" NIX_6 1195,542 r0 top
U14 "SD" TF 4459,370 r90 top locked
X1 "50M" CY_4 3565,1452 r0 top
Y1 "32.768kHz" CY_SMALL 1927,2196 r270 top

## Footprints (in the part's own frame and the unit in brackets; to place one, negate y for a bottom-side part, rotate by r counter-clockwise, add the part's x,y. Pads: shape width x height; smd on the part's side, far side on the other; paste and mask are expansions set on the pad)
0402 [mil]
  rect 25x25 smd: 1(0,0) 2(46.24,0)
  silkscreen extent -19,-21 64,21
0603 [mil]
  rect 32x32 smd: 1(0,0) 2(65,0)
  silkscreen extent -30,-30 95,30
0805 [mm]
  rect 1.1x1.36 smd: 1(0,0) 2(1.5,0)
  silkscreen extent -0.76,-0.79 2.24,0.79
1206 [mil]
  rect 60x60 smd: 1(0,0) 2(135,0)
  silkscreen extent -50,-50 185,50
1206A [mil]
  rect 60x60 smd: 1(0,0) 2(135,0)
  silkscreen extent -50,-50 190,50
AEC6.5 [mm]
  oval 3x2 smd: 1(0,0) 2(5.5,0)
  silkscreen extent -0.5,-3.25 6,3.25
BATSO [mm]
  round 1 hole 1.1: 0(-13.7,0)
  round 1 hole 1.3: 0(-6.3,0)
  rect 3x2.5 smd: 1(-1,0) 2(-18,0)
  silkscreen extent -18.06,-7.57 -1.95,7.48
BUZZER [mil]
  round 80 hole 32: 1(0,0) 2(301.57,0)
  silkscreen extent -81,-232 383,232
CY_4 [mm]
  rect 1.6x2 smd: 1(0,4.318) 2(-5.588,4.318) 3(-5.588,0) 4(0,0)
  silkscreen extent -6.88,-0.51 1.35,4.83
CY_SMALL [mil]
  rect 100x354.33 smd: 0(29,-267)
  oval 35x40 hole 20: 1(0,0) 2(60,0)
  silkscreen extent -24,-54 84,54
FTG256 [mm] "BGA, 256-Leads, Body 17x17mm, Pitch 1mm"
  round 0.45 smd: A1(-7.5,7.5) A2(-6.5,7.5) A3(-5.5,7.5) A4(-4.5,7.5) A5(-3.5,7.5) A6(-2.5,7.5) A7(-1.5,7.5) A8(-0.5,7.5) A9(0.5,7.5) A10(1.5,7.5) A11(2.5,7.5) A12(3.5,7.5) A13(4.5,7.5) A14(5.5,7.5) A15(6.5,7.5) A16(7.5,7.5) B1(-7.5,6.5) B2(-6.5,6.5) B3(-5.5,6.5) B4(-4.5,6.5) B5(-3.5,6.5) B6(-2.5,6.5) B7(-1.5,6.5) B8(-0.5,6.5) B9(0.5,6.5) B10(1.5,6.5) B11(2.5,6.5) B12(3.5,6.5) B13(4.5,6.5) B14(5.5,6.5) B15(6.5,6.5) B16(7.5,6.5) C1(-7.5,5.5) C2(-6.5,5.5) C3(-5.5,5.5) C4(-4.5,5.5) C5(-3.5,5.5) C6(-2.5,5.5) C7(-1.5,5.5) C8(-0.5,5.5) C9(0.5,5.5) C10(1.5,5.5) C11(2.5,5.5) C12(3.5,5.5) C13(4.5,5.5) C14(5.5,5.5) C15(6.5,5.5) C16(7.5,5.5) D1(-7.5,4.5) D2(-6.5,4.5) D3(-5.5,4.5) D4(-4.5,4.5) D5(-3.5,4.5) D6(-2.5,4.5) D7(-1.5,4.5) D8(-0.5,4.5) D9(0.5,4.5) D10(1.5,4.5) D11(2.5,4.5) D12(3.5,4.5) D13(4.5,4.5) D14(5.5,4.5) D15(6.5,4.5) D16(7.5,4.5) E1(-7.5,3.5) E2(-6.5,3.5) E3(-5.5,3.5) E4(-4.5,3.5) E5(-3.5,3.5) E6(-2.5,3.5) E7(-1.5,3.5) E8(-0.5,3.5) E9(0.5,3.5) E10(1.5,3.5) E11(2.5,3.5) E12(3.5,3.5) E13(4.5,3.5) E14(5.5,3.5) E15(6.5,3.5) E16(7.5,3.5) F1(-7.5,2.5) F2(-6.5,2.5) F3(-5.5,2.5) F4(-4.5,2.5) F5(-3.5,2.5) F6(-2.5,2.5) F7(-1.5,2.5) F8(-0.5,2.5) F9(0.5,2.5) F10(1.5,2.5) F11(2.5,2.5) F12(3.5,2.5) F13(4.5,2.5) F14(5.5,2.5) F15(6.5,2.5) F16(7.5,2.5) G1(-7.5,1.5) G2(-6.5,1.5) G3(-5.5,1.5) G4(-4.5,1.5) G5(-3.5,1.5) G6(-2.5,1.5) G7(-1.5,1.5) G8(-0.5,1.5) G9(0.5,1.5) G10(1.5,1.5) G11(2.5,1.5) G12(3.5,1.5) G13(4.5,1.5) G14(5.5,1.5) G15(6.5,1.5) G16(7.5,1.5) H1(-7.5,0.5) H2(-6.5,0.5) H3(-5.5,0.5) H4(-4.5,0.5) H5(-3.5,0.5) H6(-2.5,0.5) H7(-1.5,0.5) H8(-0.5,0.5) H9(0.5,0.5) H10(1.5,0.5) H11(2.5,0.5) H12(3.5,0.5) H13(4.5,0.5) H14(5.5,0.5) H15(6.5,0.5) H16(7.5,0.5) J1(-7.5,-0.5) J2(-6.5,-0.5) J3(-5.5,-0.5) J4(-4.5,-0.5) J5(-3.5,-0.5) J6(-2.5,-0.5) J7(-1.5,-0.5) J8(-0.5,-0.5) J9(0.5,-0.5) J10(1.5,-0.5) J11(2.5,-0.5) J12(3.5,-0.5) J13(4.5,-0.5) J14(5.5,-0.5) J15(6.5,-0.5) J16(7.5,-0.5) K1(-7.5,-1.5) K2(-6.5,-1.5) K3(-5.5,-1.5) K4(-4.5,-1.5) K5(-3.5,-1.5) K6(-2.5,-1.5) K7(-1.5,-1.5) K8(-0.5,-1.5) K9(0.5,-1.5) K10(1.5,-1.5) K11(2.5,-1.5) K12(3.5,-1.5) K13(4.5,-1.5) K14(5.5,-1.5) K15(6.5,-1.5) K16(7.5,-1.5) L1(-7.5,-2.5) L2(-6.5,-2.5) L3(-5.5,-2.5) L4(-4.5,-2.5) L5(-3.5,-2.5) L6(-2.5,-2.5) L7(-1.5,-2.5) L8(-0.5,-2.5) L9(0.5,-2.5) L10(1.5,-2.5) L11(2.5,-2.5) L12(3.5,-2.5) L13(4.5,-2.5) L14(5.5,-2.5) L15(6.5,-2.5) L16(7.5,-2.5) M1(-7.5,-3.5) M2(-6.5,-3.5) M3(-5.5,-3.5) M4(-4.5,-3.5) M5(-3.5,-3.5) M6(-2.5,-3.5) M7(-1.5,-3.5) M8(-0.5,-3.5) M9(0.5,-3.5) M10(1.5,-3.5) M11(2.5,-3.5) M12(3.5,-3.5) M13(4.5,-3.5) M14(5.5,-3.5) M15(6.5,-3.5) M16(7.5,-3.5) N1(-7.5,-4.5) N2(-6.5,-4.5) N3(-5.5,-4.5) N4(-4.5,-4.5) N5(-3.5,-4.5) N6(-2.5,-4.5) N7(-1.5,-4.5) N8(-0.5,-4.5) N9(0.5,-4.5) N10(1.5,-4.5) N11(2.5,-4.5) N12(3.5,-4.5) N13(4.5,-4.5) N14(5.5,-4.5) N15(6.5,-4.5) N16(7.5,-4.5) P1(-7.5,-5.5) P2(-6.5,-5.5) P3(-5.5,-5.5) P4(-4.5,-5.5) P5(-3.5,-5.5) P6(-2.5,-5.5) P7(-1.5,-5.5) P8(-0.5,-5.5) P9(0.5,-5.5) P10(1.5,-5.5) P11(2.5,-5.5) P12(3.5,-5.5) P13(4.5,-5.5) P14(5.5,-5.5) P15(6.5,-5.5) P16(7.5,-5.5) R1(-7.5,-6.5) R2(-6.5,-6.5) R3(-5.5,-6.5) R4(-4.5,-6.5) R5(-3.5,-6.5) R6(-2.5,-6.5) R7(-1.5,-6.5) R8(-0.5,-6.5) R9(0.5,-6.5) R10(1.5,-6.5) R11(2.5,-6.5) R12(3.5,-6.5) R13(4.5,-6.5) R14(5.5,-6.5) R15(6.5,-6.5) R16(7.5,-6.5) T1(-7.5,-7.5) T2(-6.5,-7.5) T3(-5.5,-7.5) T4(-4.5,-7.5) T5(-3.5,-7.5) T6(-2.5,-7.5) T7(-1.5,-7.5) T8(-0.5,-7.5) T9(0.5,-7.5) T10(1.5,-7.5) T11(2.5,-7.5) T12(3.5,-7.5) T13(4.5,-7.5) T14(5.5,-7.5) T15(6.5,-7.5) T16(7.5,-7.5)
  silkscreen extent -9.27,-8.5 8.5,8.5, body extent -8.5,-8.5 8.5,8.5, height 1.55
HDR1X2 [mm] "Connector; Header; 2 Position"
  rect 1.5x1.5 hole 0.9: 1(0,0)
  round 1.5 hole 0.9: 2(2.54,0)
  silkscreen extent -1.27,-1.27 3.81,1.27
HDR2X9 [mm] "Connector; Header; 9x2 Position"
  rect 1.5x1.5 hole 0.9: 1(0,0)
  round 1.5 hole 0.9: 2(0,2.54) 3(2.54,0) 4(2.54,2.54) 5(5.08,0) 6(5.08,2.54) 7(7.62,0) 8(7.62,2.54) 9(10.16,0) 10(10.16,2.54) 11(12.7,0) 12(12.7,2.54) 13(15.24,0) 14(15.24,2.54) 15(17.78,0) 16(17.78,2.54) 17(20.32,0) 18(20.32,2.54)
  silkscreen extent -1.27,-1.27 21.59,3.81
IDC-40J [mil]
  rect 68x68 hole 35: 1(-950,-50)
  round 68 hole 35: 2(-950,50) 3(-850,-50) 4(-850,50) 5(-750,-50) 6(-750,50) 7(-650,-50) 8(-650,50) 9(-550,-50) 10(-550,50) 11(-450,-50) 12(-450,50) 13(-350,-50) 14(-350,50) 15(-250,-50) 16(-250,50) 17(-150,-50) 18(-150,50) 19(-50,-50) 20(-50,50) 21(50,-50) 22(50,50) 23(150,-50) 24(150,50) 25(250,-50) 26(250,50) 27(350,-50) 28(350,50) 29(450,-50) 30(450,50) 31(550,-50) 32(550,50) 33(650,-50) 34(650,50) 35(750,-50) 36(750,50) 37(850,-50) 38(850,50) 39(950,-50) 40(950,50)
  silkscreen extent -1154,-167 1154,167
JTAG14-.5 [mm]
  rect 1.27x1.27 hole 0.711: 1(-6,-1)
  round 1.27 hole 0.711: 2(-6,1) 3(-4,-1) 4(-4,1) 5(-2,-1) 6(-2,1) 7(0,-1) 8(0,1) 9(2,-1) 10(2,1) 11(4,-1) 12(4,1) 13(6,-1) 14(6,1)
  silkscreen extent -10.57,-2.77 10.57,2.76
KEY735SO [mil]
  oval 140x55.12 smd: 1(0,0) 2(275,1)
  silkscreen extent 0,-67 276,71
KEY_DPDT [mil]
  round 75 hole 35: 1(0,0) 2(0,-100) 3(0,-200) 4(214.57,0) 5(214.57,-100) 6(214.57,-200)
  silkscreen extent -58,-268 277,68
LEDSO [mil]
  rect 60x50 smd: 1(90,0) 2(0,0)
  silkscreen extent -65,-40 140,40
LEDso [mil]
  rect 60x50 smd: 1(90,0) 2(0,0)
  silkscreen extent -65,-40 140,40
MINIUSBB [mm]
  rect 3x0.5 smd: 1(0,1.6) 2(0,0.8) 3(0,0) 4(0,-0.8) 5(0,-1.6)
  rect 2.5x2 smd: 6(-0.6,-4.45) 7(-6.1,-4.45) 8(-0.6,4.45) 9(-6.1,4.45)
  Keep-Out Layer circle w0.152: c-3.1,2.2 r0.5
  Keep-Out Layer circle w0.152: c-3.1,-2.2 r0.5
  silkscreen extent -9.05,-4.95 2,4.95
NIX_6 [mil]
  rect 60x60 hole 30: 1(0,0)
  round 60 hole 30: 2(100,0) 3(200,0) 4(300,0) 5(400,0) 6(500,0) 7(600,0) 8(600,400) 9(500,400) 10(400,400) 11(300,400) 12(200,400) 13(100,400) 14(0,400)
  silkscreen extent -606,-95 1206,495
QFN28 [mm]
  rect 2x2 smd: 0(2.75,-1.5)
  rect 1.2x0.27 smd: 1(0,0) 2(0,-0.5) 3(0,-1) 4(0,-1.5) 5(0,-2) 6(0,-2.5) 7(0,-3) 15(5.5,-3) 16(5.5,-2.5) 17(5.5,-2) 18(5.5,-1.5) 19(5.5,-1) 20(5.5,-0.5) 21(5.5,0)
  rect 0.27x1.2 smd: 8(1.25,-4.25) 9(1.75,-4.25) 10(2.25,-4.25) 11(2.75,-4.25) 12(3.25,-4.25) 13(3.75,-4.25) 14(4.25,-4.25) 22(4.25,1.25) 23(3.75,1.25) 24(3.25,1.25) 25(2.75,1.25) 26(2.25,1.25) 27(1.75,1.25) 28(1.25,1.25)
  silkscreen extent -0.1,-4 5.25,1.35
RN-8P [mm]
  rect 1x0.4 smd: 1(0,0) 2(0,-0.8) 3(0,-1.6) 4(0,-2.4) 5(1.858,-2.4) 6(1.858,-1.6) 7(1.858,-0.8) 8(1.858,0)
  silkscreen extent 0,-3.05 1.88,0.71
SIP2 [mil]
  rect 68x68 hole 35: 1(0,0)
  round 68 hole 35: 2(100,0)
  silkscreen extent -50,-50 150,50
SO8 [mil]
  rect 60x24 smd: 1(0,0) 2(0,-50) 3(0,-100) 4(0,-150) 5(220,-150) 6(220,-100) 7(220,-50) 8(220,0)
  silkscreen extent 40,-175 180,25
SOT23 [mil]
  rect 36x36 smd: 1(0,0) 2(75,0)
  rect 36x50 smd: 3(38,80)
  silkscreen extent -20,-5 95,85
SOT23-6 [mm]
  rect 0.5x1.27 smd: 1(0,0) 2(0.95,0) 3(1.905,0) 4(1.905,2.642) 5(0.95,2.642) 6(0,2.642)
  silkscreen extent -0.66,-0.99 2.51,3.61
SOT223 [mm]
  rect 1.2x2.2 smd: 1(0,0) 2(2.3,0) 3(4.6,0)
  rect 3.6x2.2 smd: 4(2.3,6.2)
  silkscreen extent -1.2,-1.7 5.8,7.9
TF [mm]
  rect 1.6x0.6 smd: 1(5.05,-2.25) 2(5.05,-1.15) 3(5.05,-0.05) 4(5.05,1.05) 5(5.05,2.15) 6(5.05,3.25) 7(5.05,4.35) 8(5.05,5.45) 9(5.05,6.55)
  rect 1.4x1.2 smd: 10(4.55,7.75)
  rect 2.2x1.2 smd: 11(-5.05,7.75) 12(-5.05,-7.75)
  rect 1.4x1.6 smd: 13(4.55,-6.85)
  Keep-Out Layer circle w0.127: c-5.45,4.951 r0.5
  Keep-Out Layer circle w0.127: c-5.45,-3.05 r0.5
  silkscreen extent -9.47,-7.15 4.01,7.29
TPS [mm]
  round 1.5 smd mask+0.5: 1(0,0)
TSOP-54 [mil]
  rect 17x75 smd: 1(0,0) 2(-31.5,0) 3(-62.99,0) 4(-94.49,0) 5(-125.98,0) 6(-157.48,0) 7(-188.98,0) 8(-220.47,0) 9(-251.97,0) 10(-283.46,0) 11(-314.99,0) 12(-346.46,0) 13(-377.95,0) 14(-409.45,0) 15(-440.94,0) 16(-472.44,0) 17(-503.94,0) 18(-535.43,0) 19(-566.93,0) 20(-598.43,0) 21(-629.92,0) 22(-661.42,0) 23(-692.91,0) 24(-724.41,0) 25(-755.91,0) 26(-787.4,0) 27(-818.9,0) 28(-818.9,-460) 29(-787.4,-460) 30(-755.91,-460) 31(-724.41,-460) 32(-692.91,-460) 33(-661.42,-460) 34(-630,-460) 35(-598.43,-460) 36(-566.93,-460) 37(-535.43,-460) 38(-503.94,-460) 39(-472.44,-460) 40(-440.94,-460) 41(-409.45,-460) 42(-377.95,-460) 43(-346.46,-460) 44(-314.99,-460) 45(-283.46,-460) 46(-251.97,-460) 47(-220.47,-460) 48(-188.98,-460) 49(-157.48,-460) 50(-125.98,-460) 51(-94.49,-460) 52(-62.99,-460) 53(-31.5,-460) 54(0,-460)
  silkscreen extent -852,-460 40,0
VGA [mil]
  rect 68x68 hole 35: 1(0,0)
  round 68 hole 35: 2(0,-90) 3(0,-180) 4(0,-270) 5(0,-360) 6(100,45) 7(100,-45) 8(100,-135) 9(100,-225) 10(100,-315) 11(200,0) 12(200,-90) 13(200,-180) 14(200,-270) 15(200,-360)
  round 220 hole 125: 16(100,-662) 17(100,322)
  silkscreen extent -100,-785 759,445

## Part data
C1 C2 C3 C5 C19 C46: library part "CAP NP_Dup2"
C4 C6 C7 C8 C9 C10 C11 C12 C13 C14 C15 C16 C17 C18 C20 C25 C27 C37 C44 C45 C48 C49: library part C_Dup4
C29 C30 C31 C32 C33 C34 C35: library part C_Dup2
C36: library part C_Dup3
C38 C39 C40 C41 C42 C43: library part C_Dup1
CB1: library part "Circuit Breaker", "Circuit Breaker"
EC2 EC4 EC5 EC6: library part EC
F1: library part "Fuse 2"
J1: library part MiniUSBB
J2 J3: library part MHDR2X20, "Header, 20-Pin, Dual row"
J4: library part "Connector 15", "Receptacle Assembly, 15-Pin, Sim Line Connector"
J5: "Header, 9-Pin, Dual row"
K1 K2 K3 K4 K5 K6: library part KEYB
L1: library part INDUCTOR
LED0 LED1 LED2 LED3 LED5 LED6: library part LED_Dup1
LED7 LED8: library part LED
LS1: library part SPEAKER
P1 P2 P4: library part "Header 2", "Header, 2-Pin"
P5: library part "Header 7X2", "Header, 7-Pin, Dual row"
Q1 Q2 Q3 Q4 Q5 Q6 Q7: library part PNP
R1 R8 R10 R12 R13 R14 R15 R28 R29 R30 R31 R41 R42 R43 R45 R47 R48 R49 R50 R51 R52: library part R
R2 R3 R75: library part RESISTOR
R4 R5 R6 R7 R11 R16 R32 R33 R34: library part R_Dup3
R9 R17 R20: library part R_Dup1
R18 R19 R21 R22 R35 R36 R37 R38 R39 R40 R44 R46: library part R_Dup2
R23 R24: library part R_Dup6
R25 R26 R27: library part R_Dup5
RN1 RN2 RN3 RN4 RN5 RN6 RN7 RN8 RN9 RN11 RN12 RN13 RN15 RN17 RN18 RN20 RN21 RN22 RN23 RN24 RN25 RN26 RN27 RN28 RN29 RN30 RN31 RN32 RN33: library part RN_Dup1
RN10 RN14 RN16 RN19 RN34: library part RN
SW1: library part "SW KEY-DPDT"
U4: library part CP2102_0
U5: library part 1117-3.3
U6: "Spartan-6 LX 1.2V FPGA, 186 User I/Os, 256-Ball Fine-Pitch Thin BGA (1.0mm Pitch), Speed Grade 2, Commercial Grade, Pb-Free"
U8: "16 Mb (x1) Automotive Serial NOR Flash Memory, 75 MHz, 2.7 to 3.6 V, 8-pin SO8 Narrow (MN), Tube"
U9: library part HY57651620/SO_0
U11: library part DS1302_8SO
U12: library part 24LC04B_0
X1: library part OSC
Y1: library part ZTA

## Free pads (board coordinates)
  round 250 hole 130: 0(160,160) 1(4958.11,160) 2(4958.11,3388) 3(160,3388)

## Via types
v1: diameter 20, hole 10, Top Layer to Bottom Layer, 328 vias
v2: diameter 30, hole 15, Top Layer to Bottom Layer, 95 vias
v3: diameter 40, hole 20, Top Layer to Bottom Layer, 2 vias

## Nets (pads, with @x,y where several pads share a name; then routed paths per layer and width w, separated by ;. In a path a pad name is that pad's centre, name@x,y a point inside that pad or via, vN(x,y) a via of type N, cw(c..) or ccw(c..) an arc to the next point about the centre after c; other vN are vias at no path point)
_A4: J3.3 RN22.4 | length 694.6
  Top Layer w5: J3.3@217,921.65 312.65,921.65 455.51,1064.51 RN22.4@468,1064.51 ; J3.3@228.67,909.99 cw(c256.83,881.82) 256.83,921.65 cw(c256.83,961.49) J3.3@228.67,933.32 ; J3.3@232.2,906.45 cw(c268.91,869.75) 268.91,921.65 cw(c268.91,973.56) J3.3@232.2,936.86 ; J3.3@235.74,902.92 cw(c280.98,857.68) 280.98,921.65 cw(c280.98,985.63) J3.3@235.74,940.39 ; J3.3@239.27,899.38 cw(c293.05,845.61) 293.05,921.65 cw(c293.05,997.7) J3.3@239.27,943.93 ; 445.86,1054.86 cw(c456.19,1044.53) RN22.4@456.19,1059.14 ; 447.49,1056.49 ccw(c439.48,1064.51) RN22.4@450.82,1064.51
_A5: J3.5 RN22.2 | length 679.3
  Top Layer w5: J3.5@217,1021.65 321.65,1021.65 427.5,1127.5 RN22.2@468,1127.5 ; J3.5@228.67,1009.99 cw(c256.83,981.82) 256.83,1021.65 cw(c256.83,1061.49) J3.5@228.67,1033.32 ; J3.5@232.2,1006.45 cw(c268.91,969.75) 268.91,1021.65 cw(c268.91,1073.56) J3.5@232.2,1036.86 ; J3.5@235.74,1002.92 cw(c280.98,957.68) 280.98,1021.65 cw(c280.98,1085.63) J3.5@235.74,1040.39 ; J3.5@239.27,999.38 cw(c293.05,945.61) 293.05,1021.65 cw(c293.05,1097.7) J3.5@239.27,1043.93 ; RN22.2@452.39,1123.7 ccw(c443.21,1114.53) 443.21,1127.5 ccw(c443.21,1140.48) RN22.2@452.39,1131.3
_A6: J3.7 RN21.4 | length 726.2
  Top Layer w5: J3.7@217,1121.65 338.65,1121.65 446.89,1229.89 ; J3.7@228.67,1109.99 cw(c256.83,1081.82) 256.83,1121.65 cw(c256.83,1161.49) J3.7@228.67,1133.32 ; J3.7@232.2,1106.45 cw(c268.91,1069.75) 268.91,1121.65 cw(c268.91,1173.56) J3.7@232.2,1136.86 ; J3.7@235.74,1102.92 cw(c280.98,1057.68) 280.98,1121.65 cw(c280.98,1185.63) J3.7@235.74,1140.39 ; J3.7@239.27,1099.38 cw(c293.05,1045.61) 293.05,1121.65 cw(c293.05,1197.7) J3.7@239.27,1143.93 ; 431.14,1214.13 cw(c456.19,1189.08) RN21.4@456.19,1224.51 ; 439.67,1222.67 cw(c456.19,1206.15) RN21.4@456.19,1229.51 ; 448.21,1231.21 cw(c456.19,1223.22) RN21.4@456.19,1234.51 ; RN21.4@451.53,1227.2 ccw(c446.89,1224.52) 446.89,1229.89 ; RN21.4@451.53,1232.57 cw(c446.89,1235.25) 446.89,1229.89 ; RN21.4@468,1229.89 446.89,1229.89
_A7: J3.8 RN21.3 | length 726.3
  Top Layer w5: J3.8@117,1121.65 164.35,1169 ; J3.8@118.55,1138.08 ccw(c121.28,1166.97) 141.8,1146.45 ccw(c162.32,1125.93) J3.8@133.43,1123.2 ; J3.8@119.02,1143.06 ccw(c122.57,1180.71) 149.31,1153.97 ccw(c176.06,1127.23) J3.8@138.4,1123.67 ; J3.8@119.49,1148.04 ccw(c123.87,1194.44) 156.83,1161.48 ccw(c189.79,1128.52) J3.8@143.38,1124.14 ; J3.8@119.96,1153.01 ccw(c125.17,1208.18) 164.34,1169 ; J3.8@148.36,1124.61 cw(c203.52,1129.82) 164.34,1169 ; RN21.3@452.39,1257.58 ccw(c443.21,1248.41) 443.21,1261.38 ccw(c443.21,1274.36) RN21.3@452.39,1265.18 ; RN21.3@468,1261.38 438.38,1261.38 346,1169 164.35,1169
_A8: J3.10 RN21.1 | length 732.1
  Top Layer w5: J3.10@117,1221.65 166.35,1271 ; J3.10@118.03,1238.12 ccw(c120.05,1270.3) 142.85,1247.5 ccw(c165.64,1224.7) J3.10@133.47,1222.69 ; J3.10@118.35,1243.11 ccw(c120.98,1285.04) 150.68,1255.33 ccw(c180.38,1225.63) J3.10@138.46,1223 ; J3.10@118.66,1248.1 ccw(c121.9,1299.78) 158.51,1263.16 ccw(c195.12,1226.55) J3.10@143.45,1223.31 ; J3.10@118.97,1253.09 ccw(c122.82,1314.52) 166.34,1271 ; J3.10@148.44,1223.63 cw(c209.86,1227.48) 166.34,1271 ; RN21.1@452.39,1320.58 ccw(c443.21,1311.4) 443.21,1324.38 ccw(c443.21,1337.35) RN21.1@452.39,1328.17 ; RN21.1@468,1324.38 417.38,1324.38 364,1271 166.35,1271
_A9: J3.12 RN20.3 | length 753.9
  Top Layer w5: J3.12@117,1321.65 168.35,1373 ; J3.12@117.55,1338.14 ccw(c118.73,1373.71) 143.89,1348.55 ccw(c169.06,1323.38) J3.12@133.49,1322.2 ; J3.12@117.71,1343.14 ccw(c119.26,1389.49) 152.04,1356.7 ccw(c184.83,1323.91) J3.12@138.49,1322.37 ; J3.12@117.88,1348.14 ccw(c119.78,1405.26) 160.19,1364.85 ccw(c200.61,1324.43) J3.12@143.49,1322.53 ; J3.12@118.05,1353.14 ccw(c120.3,1421.04) 168.34,1373 ; J3.12@148.48,1322.7 cw(c216.38,1324.96) 168.34,1373 ; RN20.3@452.39,1422.96 ccw(c443.21,1413.78) 443.21,1426.76 ccw(c443.21,1439.73) RN20.3@452.39,1430.56 ; RN20.3@468,1426.76 439.76,1426.76 386,1373 168.35,1373
_A10: J3.13 RN20.2 | length 650.6
  Top Layer w5: J3.13@217,1421.65 396.65,1421.65 433.25,1458.25 RN20.2@468,1458.25 ; J3.13@228.67,1409.99 cw(c256.83,1381.82) 256.83,1421.65 cw(c256.83,1461.49) J3.13@228.67,1433.32 ; J3.13@232.2,1406.45 cw(c268.91,1369.75) 268.91,1421.65 cw(c268.91,1473.56) J3.13@232.2,1436.86 ; J3.13@235.74,1402.92 cw(c280.98,1357.68) 280.98,1421.65 cw(c280.98,1485.63) J3.13@235.74,1440.39 ; J3.13@239.27,1399.38 cw(c293.05,1345.61) 293.05,1421.65 cw(c293.05,1497.7) J3.13@239.27,1443.93 ; RN20.2@452.39,1454.45 ccw(c443.21,1445.28) 443.21,1458.25 ccw(c443.21,1471.23) RN20.2@452.39,1462.05
_A11: J3.15 RN18.4 | length 651.6
  Top Layer w5: J3.15@217,1521.65 402.65,1521.65 441.64,1560.64 RN18.4@468,1560.64 ; J3.15@228.67,1509.99 cw(c256.83,1481.82) 256.83,1521.65 cw(c256.83,1561.49) J3.15@228.67,1533.32 ; J3.15@232.2,1506.45 cw(c268.91,1469.75) 268.91,1521.65 cw(c268.91,1573.56) J3.15@232.2,1536.86 ; J3.15@235.74,1502.92 cw(c280.98,1457.68) 280.98,1521.65 cw(c280.98,1585.63) J3.15@235.74,1540.39 ; J3.15@239.27,1499.38 cw(c293.05,1445.61) 293.05,1521.65 cw(c293.05,1597.7) J3.15@239.27,1543.93 ; RN18.4@452.39,1556.84 ccw(c443.21,1547.66) 443.21,1560.64 ccw(c443.21,1573.61) RN18.4@452.39,1564.44
_A12: J3.16 RN18.3 | length 739.6
  Top Layer w5: J3.16@117,1521.65 168.35,1573 ; J3.16@117.55,1538.14 ccw(c118.73,1573.71) 143.89,1548.55 ccw(c169.06,1523.38) J3.16@133.49,1522.2 ; J3.16@117.71,1543.14 ccw(c119.26,1589.49) 152.04,1556.7 ccw(c184.83,1523.91) J3.16@138.49,1522.37 ; J3.16@117.88,1548.14 ccw(c119.78,1605.26) 160.19,1564.85 ccw(c200.61,1524.43) J3.16@143.49,1522.53 ; J3.16@118.05,1553.14 ccw(c120.3,1621.04) 168.34,1573 ; J3.16@148.48,1522.7 cw(c216.38,1524.96) 168.34,1573 ; RN18.3@452.39,1588.33 ccw(c443.21,1579.16) 443.21,1592.13 ccw(c443.21,1605.11) RN18.3@452.39,1595.93 ; RN18.3@468,1592.13 439.13,1592.13 420,1573 168.35,1573
_A13: J3.18 RN18.1 | length 705.2
  Top Layer w5: J3.18@117,1621.65 165.35,1670 ; J3.18@118.29,1638.1 ccw(c120.68,1668.62) 142.32,1646.98 ccw(c163.97,1625.33) J3.18@133.45,1622.94 ; J3.18@118.68,1643.09 ccw(c121.79,1682.86) 150,1654.65 ccw(c178.21,1626.44) J3.18@138.43,1623.33 ; J3.18@119.07,1648.07 ccw(c122.9,1697.09) 157.67,1662.32 ccw(c192.44,1627.56) J3.18@143.42,1623.72 ; J3.18@119.46,1653.06 ccw(c124.02,1711.33) 165.34,1670 ; J3.18@148.4,1624.11 cw(c206.67,1628.67) 165.34,1670 ; RN18.1@452.39,1651.33 ccw(c443.21,1642.15) 443.21,1655.12 ccw(c443.21,1668.1) RN18.1@452.39,1658.92 ; RN18.1@468,1655.12 439.88,1655.12 425,1670 165.35,1670
_A14: J3.19 RN17.4 | length 651.1
  Top Layer w5: J3.19@217,1721.65 221.36,1726.01 RN17.4@468,1726.01 ; J3.19@225.13,1713.52 cw(c255.29,1683.37) 255.29,1726.01 ; J3.19@228.67,1709.99 cw(c267.36,1671.3) 267.36,1726.01 ; J3.19@232.2,1706.45 cw(c279.43,1659.23) 279.43,1726.01 ; J3.19@232.2,1736.86 ccw(c258.38,1763.04) 258.38,1726.01 ; J3.19@235.74,1702.92 cw(c291.5,1647.16) 291.5,1726.01 ; J3.19@235.74,1740.39 ccw(c270.45,1775.11) 270.45,1726.01 ; J3.19@239.27,1699.38 cw(c303.57,1635.08) 303.57,1726.01 ; J3.19@239.27,1743.93 ccw(c282.53,1787.18) 282.53,1726.01 ; RN17.4@452.39,1722.21 ccw(c443.21,1713.04) 443.21,1726.01 ccw(c443.21,1738.99) RN17.4@452.39,1729.81
_B5: J3.4 RN22.3 | length 761.7
  Top Layer w5: J3.4@117,921.65 166.35,971 ; J3.4@118.03,938.12 ccw(c120.05,970.3) 142.85,947.5 ccw(c165.64,924.7) J3.4@133.47,922.69 ; J3.4@118.35,943.11 ccw(c120.98,985.04) 150.68,955.33 ccw(c180.38,925.63) J3.4@138.46,923 ; J3.4@118.66,948.1 ccw(c121.9,999.78) 158.51,963.16 ccw(c195.12,926.55) J3.4@143.45,923.31 ; J3.4@118.97,953.09 ccw(c122.82,1014.52) 166.34,971 ; J3.4@148.44,923.63 cw(c209.86,927.48) 166.34,971 ; RN22.3@452.39,1092.21 ccw(c443.21,1083.03) 443.21,1096.01 ccw(c443.21,1108.98) RN22.3@452.39,1099.81 ; RN22.3@468,1096.01 443.01,1096.01 318,971 166.35,971
_B6: J3.6 RN22.1 | length 756.9
  Top Layer w5: J3.6@117,1021.65 167.35,1072 ; J3.6@117.79,1038.13 ccw(c119.4,1071.99) 143.37,1048.02 ccw(c167.34,1024.06) J3.6@133.48,1022.44 ; J3.6@118.02,1043.13 ccw(c120.13,1087.25) 151.36,1056.02 ccw(c182.59,1024.78) J3.6@138.48,1022.68 ; J3.6@118.26,1048.12 ccw(c120.86,1102.5) 159.35,1064.01 ccw(c197.85,1025.51) J3.6@143.47,1022.92 ; J3.6@118.5,1053.12 ccw(c121.59,1117.76) 167.34,1072 ; J3.6@148.46,1023.15 cw(c213.1,1026.24) 167.34,1072 ; RN22.1@452.39,1155.2 ccw(c443.21,1146.03) 443.21,1159 ccw(c443.21,1171.97) RN22.1@452.39,1162.8 ; RN22.1@468,1159 414,1159 327,1072 167.35,1072
_B8: J3.9 RN21.2 | length 664.9
  Top Layer w5: J3.9@217,1221.65 356.65,1221.65 427.88,1292.88 RN21.2@468,1292.88 ; J3.9@228.67,1209.99 cw(c256.83,1181.82) 256.83,1221.65 cw(c256.83,1261.49) J3.9@228.67,1233.32 ; J3.9@232.2,1206.45 cw(c268.91,1169.75) 268.91,1221.65 cw(c268.91,1273.56) J3.9@232.2,1236.86 ; J3.9@235.74,1202.92 cw(c280.98,1157.68) 280.98,1221.65 cw(c280.98,1285.63) J3.9@235.74,1240.39 ; J3.9@239.27,1199.38 cw(c293.05,1145.61) 293.05,1221.65 cw(c293.05,1297.7) J3.9@239.27,1243.93 ; RN21.2@452.39,1289.08 ccw(c443.21,1279.9) 443.21,1292.88 ccw(c443.21,1305.85) RN21.2@452.39,1296.68
_B10: J3.14 RN20.1 | length 707.2
  Top Layer w5: J3.14@117,1421.65 165.35,1470 ; J3.14@118.29,1438.1 ccw(c120.68,1468.62) 142.32,1446.98 ccw(c163.97,1425.33) J3.14@133.45,1422.94 ; J3.14@118.68,1443.09 ccw(c121.79,1482.86) 150,1454.65 ccw(c178.21,1426.44) J3.14@138.43,1423.33 ; J3.14@119.07,1448.07 ccw(c122.9,1497.09) 157.67,1462.32 ccw(c192.44,1427.56) J3.14@143.42,1423.72 ; J3.14@119.46,1453.06 ccw(c124.02,1511.33) 165.34,1470 ; J3.14@148.4,1424.11 cw(c206.67,1428.67) 165.34,1470 ; RN20.1@452.39,1485.95 ccw(c443.21,1476.78) 443.21,1489.75 ccw(c443.21,1502.72) RN20.1@452.39,1493.55 ; RN20.1@468,1489.75 421.75,1489.75 402,1470 165.35,1470
_B12: J3.17 RN18.2 | length 636.3
  Top Layer w5: J3.17@217,1621.65 218.98,1623.63 RN18.2@468,1623.63 ; J3.17@228.67,1609.99 cw(c261.6,1577.05) 261.6,1623.63 ; J3.17@228.67,1633.32 ccw(c252.07,1656.72) 252.07,1623.63 ; J3.17@232.2,1606.45 cw(c273.67,1564.98) 273.67,1623.63 ; J3.17@232.2,1636.86 ccw(c264.14,1668.79) 264.14,1623.63 ; J3.17@235.74,1602.92 cw(c285.75,1552.91) 285.75,1623.63 ; J3.17@235.74,1640.39 ccw(c276.21,1680.86) 276.21,1623.63 ; J3.17@239.27,1599.38 cw(c297.82,1540.84) 297.82,1623.63 ; J3.17@239.27,1643.93 ccw(c288.28,1692.93) 288.28,1623.63 ; RN18.2@452.39,1619.83 ccw(c443.21,1610.65) 443.21,1623.63 ccw(c443.21,1636.6) RN18.2@452.39,1627.43
_B14: J3.20 RN17.3 | length 715.5
  Top Layer w5: J3.20@117,1721.65 166.35,1771 ; J3.20@118.03,1738.12 ccw(c120.05,1770.3) 142.85,1747.5 ccw(c165.64,1724.7) J3.20@133.47,1722.69 ; J3.20@118.35,1743.11 ccw(c120.98,1785.04) 150.68,1755.33 ccw(c180.38,1725.63) J3.20@138.46,1723 ; J3.20@118.66,1748.1 ccw(c121.9,1799.78) 158.51,1763.16 ccw(c195.12,1726.55) J3.20@143.45,1723.31 ; J3.20@118.97,1753.09 ccw(c122.82,1814.52) 166.34,1771 ; J3.20@148.44,1723.63 cw(c209.86,1727.48) 166.34,1771 ; RN17.3@452.39,1753.71 ccw(c443.21,1744.53) 443.21,1757.51 ccw(c443.21,1770.48) RN17.3@452.39,1761.31 ; RN17.3@468,1757.51 383.49,1757.51 370,1771 166.35,1771
_B15: J3.21 RN17.2 | length 649
  Top Layer w5: J3.21@217,1821.65 359.35,1821.65 392,1789 RN17.2@468,1789 ; J3.21@228.67,1809.99 cw(c256.83,1781.82) 256.83,1821.65 cw(c256.83,1861.49) J3.21@228.67,1833.32 ; J3.21@232.2,1806.45 cw(c268.91,1769.75) 268.91,1821.65 cw(c268.91,1873.56) J3.21@232.2,1836.86 ; J3.21@235.74,1802.92 cw(c280.98,1757.68) 280.98,1821.65 cw(c280.98,1885.63) J3.21@235.74,1840.39 ; J3.21@239.27,1799.38 cw(c293.05,1745.61) 293.05,1821.65 cw(c293.05,1897.7) J3.21@239.27,1843.93 ; RN17.2@452.39,1785.2 ccw(c443.21,1776.03) 443.21,1789 ccw(c443.21,1801.98) RN17.2@452.39,1792.8
_B16: J3.22 RN17.1 | length 742.2
  Top Layer w5: J3.22@117,1821.65 167.35,1872 ; J3.22@117.79,1838.13 ccw(c119.4,1871.99) 143.37,1848.02 ccw(c167.34,1824.06) J3.22@133.48,1822.44 ; J3.22@118.02,1843.13 ccw(c120.13,1887.25) 151.36,1856.02 ccw(c182.59,1824.78) J3.22@138.48,1822.68 ; J3.22@118.26,1848.12 ccw(c120.86,1902.5) 159.35,1864.01 ccw(c197.85,1825.51) J3.22@143.47,1822.92 ; J3.22@118.5,1853.12 ccw(c121.59,1917.76) 167.34,1872 ; J3.22@148.46,1823.15 cw(c213.1,1826.24) 167.34,1872 ; RN17.1@452.39,1816.7 ccw(c443.21,1807.53) 443.21,1820.5 ccw(c443.21,1833.47) RN17.1@452.39,1824.3 ; RN17.1@468,1820.5 392.5,1820.5 341,1872 167.35,1872
_C8: J3.11 RN20.4 | length 665.9
  Top Layer w5: J3.11@217,1321.65 366.65,1321.65 440.26,1395.26 RN20.4@468,1395.26 ; J3.11@228.67,1309.99 cw(c256.83,1281.82) 256.83,1321.65 cw(c256.83,1361.49) J3.11@228.67,1333.32 ; J3.11@232.2,1306.45 cw(c268.91,1269.75) 268.91,1321.65 cw(c268.91,1373.56) J3.11@232.2,1336.86 ; J3.11@235.74,1302.92 cw(c280.98,1257.68) 280.98,1321.65 cw(c280.98,1385.63) J3.11@235.74,1340.39 ; J3.11@239.27,1299.38 cw(c293.05,1245.61) 293.05,1321.65 cw(c293.05,1397.7) J3.11@239.27,1343.93 ; RN20.4@452.39,1391.46 ccw(c443.21,1382.29) 443.21,1395.26 ccw(c443.21,1408.24) RN20.4@452.39,1399.06
_C9: J3.27 RN13.4 | length 662.3
  Top Layer w5: J3.27@217,2121.65 332.35,2121.65 397.24,2056.76 RN13.4@468,2056.76 ; J3.27@228.67,2109.99 cw(c256.83,2081.82) 256.83,2121.65 cw(c256.83,2161.49) J3.27@228.67,2133.32 ; J3.27@232.2,2106.45 cw(c268.91,2069.75) 268.91,2121.65 cw(c268.91,2173.56) J3.27@232.2,2136.86 ; J3.27@235.74,2102.92 cw(c280.98,2057.68) 280.98,2121.65 cw(c280.98,2185.63) J3.27@235.74,2140.39 ; J3.27@239.27,2099.38 cw(c293.05,2045.61) 293.05,2121.65 cw(c293.05,2197.7) J3.27@239.27,2143.93 ; RN13.4@452.39,2052.96 ccw(c443.21,2043.79) 443.21,2056.76 ccw(c443.21,2069.74) RN13.4@452.39,2060.56
_C10: J3.29 RN13.2 | length 677.6
  Top Layer w5: J3.29@217,2221.65 301.35,2221.65 403.25,2119.75 RN13.2@468,2119.75 ; J3.29@228.67,2209.99 cw(c256.83,2181.82) 256.83,2221.65 cw(c256.83,2261.49) J3.29@228.67,2233.32 ; J3.29@232.2,2206.45 cw(c268.91,2169.75) 268.91,2221.65 cw(c268.91,2273.56) J3.29@232.2,2236.86 ; J3.29@235.74,2202.92 cw(c280.98,2157.68) 280.98,2221.65 cw(c280.98,2285.63) J3.29@235.74,2240.39 ; J3.29@239.27,2199.38 cw(c293.05,2145.61) 293.05,2221.65 cw(c293.05,2297.7) J3.29@239.27,2243.93 ; RN13.2@452.39,2115.95 ccw(c443.21,2106.78) 443.21,2119.75 ccw(c443.21,2132.73) RN13.2@452.39,2123.55
_C15: J3.23 RN15.4 | length 648
  Top Layer w5: J3.23@217,1921.65 354.35,1921.65 384.61,1891.39 RN15.4@468,1891.39 ; J3.23@228.67,1909.99 cw(c256.83,1881.82) 256.83,1921.65 cw(c256.83,1961.49) J3.23@228.67,1933.32 ; J3.23@232.2,1906.45 cw(c268.91,1869.75) 268.91,1921.65 cw(c268.91,1973.56) J3.23@232.2,1936.86 ; J3.23@235.74,1902.92 cw(c280.98,1857.68) 280.98,1921.65 cw(c280.98,1985.63) J3.23@235.74,1940.39 ; J3.23@239.27,1899.38 cw(c293.05,1845.61) 293.05,1921.65 cw(c293.05,1997.7) J3.23@239.27,1943.93 ; RN15.4@452.39,1887.59 ccw(c443.21,1878.41) 443.21,1891.39 ccw(c443.21,1904.36) RN15.4@452.39,1895.19
_C16: J3.24 RN15.3 | length 741.2
  Top Layer w5: J3.24@117,1921.65 167.35,1972 ; J3.24@117.79,1938.13 ccw(c119.4,1971.99) 143.37,1948.02 ccw(c167.34,1924.06) J3.24@133.48,1922.44 ; J3.24@118.02,1943.13 ccw(c120.13,1987.25) 151.36,1956.02 ccw(c182.59,1924.78) J3.24@138.48,1922.68 ; J3.24@118.26,1948.12 ccw(c120.86,2002.5) 159.35,1964.01 ccw(c197.85,1925.51) J3.24@143.47,1922.92 ; J3.24@118.5,1953.12 ccw(c121.59,2017.76) 167.34,1972 ; J3.24@148.46,1923.15 cw(c213.1,1926.24) 167.34,1972 ; RN15.3@452.39,1919.08 ccw(c443.21,1909.91) 443.21,1922.88 ccw(c443.21,1935.86) RN15.3@452.39,1926.68 ; RN15.3@468,1922.88 394.12,1922.88 345,1972 167.35,1972
_D11: J3.30 RN13.1 | length 770.8
  Top Layer w5: J3.30@117,2221.65 167.35,2272 ; J3.30@117.79,2238.13 ccw(c119.4,2271.99) 143.37,2248.02 ccw(c167.34,2224.06) J3.30@133.48,2222.44 ; J3.30@118.02,2243.13 ccw(c120.13,2287.25) 151.36,2256.02 ccw(c182.59,2224.78) J3.30@138.48,2222.68 ; J3.30@118.26,2248.12 ccw(c120.86,2302.5) 159.35,2264.01 ccw(c197.85,2225.51) J3.30@143.47,2222.92 ; J3.30@118.5,2253.12 ccw(c121.59,2317.76) 167.34,2272 ; J3.30@148.46,2223.15 cw(c213.1,2226.24) 167.34,2272 ; RN13.1@452.39,2147.45 ccw(c443.21,2138.28) 443.21,2151.25 ccw(c443.21,2164.22) RN13.1@452.39,2155.05 ; RN13.1@468,2151.25 403.75,2151.25 283,2272 167.35,2272
_D16: J3.25 RN15.2 | length 663.3
  Top Layer w5: J3.25@217,2021.65 340.35,2021.65 407.62,1954.38 RN15.2@468,1954.38 ; J3.25@228.67,2009.99 cw(c256.83,1981.82) 256.83,2021.65 cw(c256.83,2061.49) J3.25@228.67,2033.32 ; J3.25@232.2,2006.45 cw(c268.91,1969.75) 268.91,2021.65 cw(c268.91,2073.56) J3.25@232.2,2036.86 ; J3.25@235.74,2002.92 cw(c280.98,1957.68) 280.98,2021.65 cw(c280.98,2085.63) J3.25@235.74,2040.39 ; J3.25@239.27,1999.38 cw(c293.05,1945.61) 293.05,2021.65 cw(c293.05,2097.7) J3.25@239.27,2043.93 ; RN15.2@452.39,1950.58 ccw(c443.21,1941.4) 443.21,1954.38 ccw(c443.21,1967.35) RN15.2@452.39,1958.18
_E11: J3.28 RN13.3 | length 732.9
  Top Layer w5: J3.28@117,2121.65 165.35,2170 ; J3.28@118.29,2138.1 ccw(c120.68,2168.62) 142.32,2146.98 ccw(c163.97,2125.33) J3.28@133.45,2122.94 ; J3.28@118.68,2143.09 ccw(c121.79,2182.86) 150,2154.65 ccw(c178.21,2126.44) J3.28@138.43,2123.33 ; J3.28@119.07,2148.07 ccw(c122.9,2197.09) 157.67,2162.32 ccw(c192.44,2127.56) J3.28@143.42,2123.72 ; J3.28@119.46,2153.06 ccw(c124.02,2211.33) 165.34,2170 ; J3.28@148.4,2124.11 cw(c206.67,2128.67) 165.34,2170 ; RN13.3@452.39,2084.46 ccw(c443.21,2075.28) 443.21,2088.26 ccw(c443.21,2101.23) RN13.3@452.39,2092.06 ; RN13.3@468,2088.26 401.74,2088.26 320,2170 165.35,2170
_E15: J3.26 RN15.1 | length 722.4
  Top Layer w5: J3.26@117,2021.65 164.35,2069 ; J3.26@118.55,2038.08 ccw(c121.28,2066.97) 141.8,2046.45 ccw(c162.32,2025.93) J3.26@133.43,2023.2 ; J3.26@119.02,2043.06 ccw(c122.57,2080.71) 149.31,2053.97 ccw(c176.06,2027.23) J3.26@138.4,2023.67 ; J3.26@119.49,2048.04 ccw(c123.87,2094.44) 156.83,2061.48 ccw(c189.79,2028.52) J3.26@143.38,2024.14 ; J3.26@119.96,2053.01 ccw(c125.17,2108.18) 164.34,2069 ; J3.26@148.36,2024.61 cw(c203.52,2029.82) 164.34,2069 ; RN15.1@452.39,1982.08 ccw(c443.21,1972.9) 443.21,1985.88 ccw(c443.21,1998.85) RN15.1@452.39,1989.67 ; RN15.1@468,1985.88 413.12,1985.88 330,2069 164.35,2069
_E16: J3.31 RN12.4 | length 612.5
  Top Layer w5: J3.31@217,2321.65 284.35,2321.65 ; J3.31@229.66,2311.08 cw(c252.28,2292.2) 252.28,2321.65 cw(c252.28,2351.11) J3.31@229.66,2332.23 ; J3.31@233.5,2307.87 cw(c262.96,2283.27) 262.96,2321.65 cw(c262.96,2360.04) J3.31@233.5,2335.43 ; J3.31@237.34,2304.67 cw(c273.65,2274.34) 273.65,2321.65 cw(c273.65,2368.96) J3.31@237.34,2338.64 ; J3.31@241.18,2301.46 cw(c284.34,2265.42) 284.34,2321.65 ; J3.31@241.18,2341.84 ccw(c284.34,2377.89) 284.34,2321.65 ; RN12.4@452.39,2218.34 ccw(c443.21,2209.16) 443.21,2222.14 ccw(c443.21,2235.11) RN12.4@452.39,2225.94 ; RN12.4@468,2222.14 383.86,2222.14 284.35,2321.65
_F15: J3.32 RN12.3 | length 747.2
  Top Layer w5: J3.32@117,2321.65 165.35,2370 ; J3.32@118.29,2338.1 ccw(c120.68,2368.62) 142.32,2346.98 ccw(c163.97,2325.33) J3.32@133.45,2322.94 ; J3.32@118.68,2343.09 ccw(c121.79,2382.86) 150,2354.65 ccw(c178.21,2326.44) J3.32@138.43,2323.33 ; J3.32@119.07,2348.07 ccw(c122.9,2397.09) 157.67,2362.32 ccw(c192.44,2327.56) J3.32@143.42,2323.72 ; J3.32@119.46,2353.06 ccw(c124.02,2411.33) 165.34,2370 ; J3.32@148.4,2324.11 cw(c206.67,2328.67) 165.34,2370 ; RN12.3@452.39,2249.83 ccw(c443.21,2240.66) 443.21,2253.63 ccw(c443.21,2266.61) RN12.3@452.39,2257.43 ; RN12.3@468,2253.63 393.37,2253.63 277,2370 165.35,2370
_F16: J3.33 RN12.2 | length 479.6
  Top Layer w5: J3.33@217,2421.65 269.35,2421.65 ; J3.33@236,2411.59 cw(c252.73,2402.72) 252.73,2421.65 cw(c252.73,2440.59) J3.33@236,2431.72 ; J3.33@240.41,2409.24 cw(c261.04,2398.32) 261.04,2421.65 cw(c261.04,2444.99) J3.33@240.41,2434.06 ; J3.33@244.83,2406.9 cw(c269.34,2393.91) 269.34,2421.65 ; J3.33@244.83,2436.4 ccw(c269.34,2449.39) 269.34,2421.65 ; RN12.2@452.39,2281.33 ccw(c443.21,2272.15) 443.21,2285.13 ccw(c443.21,2298.1) RN12.2@452.39,2288.93 ; RN12.2@468,2285.13 405.87,2285.13 269.35,2421.65
_G16: J3.34 RN12.1 | length 762.5
  Top Layer w5: J3.34@117,2421.65 165.35,2470 ; J3.34@118.29,2438.1 ccw(c120.68,2468.62) 142.32,2446.98 ccw(c163.97,2425.33) J3.34@133.45,2422.94 ; J3.34@118.68,2443.09 ccw(c121.79,2482.86) 150,2454.65 ccw(c178.21,2426.44) J3.34@138.43,2423.33 ; J3.34@119.07,2448.07 ccw(c122.9,2497.09) 157.67,2462.32 ccw(c192.44,2427.56) J3.34@143.42,2423.72 ; J3.34@119.46,2453.06 ccw(c124.02,2511.33) 165.34,2470 ; J3.34@148.4,2424.11 cw(c206.67,2428.67) 165.34,2470 ; RN12.1@452.39,2312.83 ccw(c443.21,2303.65) 443.21,2316.62 ccw(c443.21,2329.6) RN12.1@452.39,2320.42 ; RN12.1@468,2316.62 410.38,2316.62 257,2470 165.35,2470
_H15: J3.35 RN11.4 | length 691
  Top Layer w5: J3.35@217,2521.65 307.35,2521.65 441.49,2387.51 RN11.4@468,2387.51 ; J3.35@228.67,2509.99 cw(c256.83,2481.82) 256.83,2521.65 cw(c256.83,2561.49) J3.35@228.67,2533.32 ; J3.35@232.2,2506.45 cw(c268.91,2469.75) 268.91,2521.65 cw(c268.91,2573.56) J3.35@232.2,2536.86 ; J3.35@235.74,2502.92 cw(c280.98,2457.68) 280.98,2521.65 cw(c280.98,2585.63) J3.35@235.74,2540.39 ; J3.35@239.27,2499.38 cw(c293.05,2445.61) 293.05,2521.65 cw(c293.05,2597.7) J3.35@239.27,2543.93 ; RN11.4@452.39,2383.71 ccw(c443.21,2374.54) 443.21,2387.51 ccw(c443.21,2400.49) RN11.4@452.39,2391.31
_H16: J3.36 RN11.3 | length 759.7
  Top Layer w5: J3.36@117,2521.65 165.35,2570 ; J3.36@118.29,2538.1 ccw(c120.68,2568.62) 142.32,2546.98 ccw(c163.97,2525.33) J3.36@133.45,2522.94 ; J3.36@118.68,2543.09 ccw(c121.79,2582.86) 150,2554.65 ccw(c178.21,2526.44) J3.36@138.43,2523.33 ; J3.36@119.07,2548.07 ccw(c122.9,2597.09) 157.67,2562.32 ccw(c192.44,2527.56) J3.36@143.42,2523.72 ; J3.36@119.46,2553.06 ccw(c124.02,2611.33) 165.34,2570 ; J3.36@148.4,2524.11 cw(c206.67,2528.67) 165.34,2570 ; RN11.3@452.22,2415.38 ccw(c443.99,2407.86) 443.99,2419.01 ; RN11.3@452.22,2422.63 cw(c443.99,2430.16) 443.99,2419.01 ; RN11.3@468,2419.01 443.99,2419.01 ; 165.35,2570 293,2570 443.99,2419.01
_J16: J2.4 RN1.8 | length 764.6
  Top Layer w5: RN1.8@4646.15,2482 4669,2482 ; RN1.8@4662.19,2478.69 cw(c4669,2473.35) 4669,2482 ; RN1.8@4662.19,2485.31 ccw(c4669,2490.65) 4669,2482 ; J2.4@4969.64,2624.61 ccw(c4914.48,2629.82) 4953.66,2669 ; J2.4@4974.62,2624.14 ccw(c4928.21,2628.52) 4961.17,2661.48 ccw(c4994.13,2694.44) J2.4@4998.51,2648.04 ; J2.4@4979.6,2623.67 ccw(c4941.94,2627.23) 4968.69,2653.97 ccw(c4995.43,2680.71) J2.4@4998.98,2643.06 ; J2.4@4984.57,2623.2 ccw(c4955.68,2625.93) 4976.2,2646.45 ccw(c4996.72,2666.97) J2.4@4999.45,2638.08 ; J2.4@4998.04,2653.01 cw(c4992.83,2708.18) 4953.66,2669 ; J2.4@5001,2621.65 4953.65,2669 ; 4669,2482 4856,2669 4953.65,2669
_K15: J2.6 RN1.6 | length 788.1
  Top Layer w5: RN1.6@4646.15,2419.01 4688.01,2419.01 4841,2572 4950.65,2572 ; RN1.6@4661.76,2415.21 cw(c4670.94,2406.03) 4670.94,2419.01 cw(c4670.94,2431.98) RN1.6@4661.76,2422.81 ; J2.6@4969.54,2523.15 ccw(c4904.9,2526.24) 4950.66,2572 ; J2.6@4974.53,2522.92 ccw(c4920.15,2525.51) 4958.65,2564.01 ccw(c4997.14,2602.5) J2.6@4999.74,2548.12 ; J2.6@4979.52,2522.68 ccw(c4935.41,2524.78) 4966.64,2556.02 ccw(c4997.87,2587.25) J2.6@4999.98,2543.13 ; J2.6@4984.52,2522.44 ccw(c4950.66,2524.06) 4974.63,2548.02 ccw(c4998.6,2571.99) J2.6@5000.21,2538.13 ; J2.6@4999.5,2553.12 cw(c4996.41,2617.76) 4950.66,2572 ; J2.6@5001,2521.65 4950.65,2572
_K16: J2.3 RN1.7 | length 484.3
  Top Layer w5: RN1.7@4646.15,2450.5 4679.5,2450.5 4850.65,2621.65 ; RN1.7@4661.76,2446.7 cw(c4670.94,2437.53) 4670.94,2450.5 cw(c4670.94,2463.48) RN1.7@4661.76,2454.3 ; J2.3@4872.67,2607.88 ccw(c4850.65,2597.17) 4850.65,2621.65 ; J2.3@4872.67,2635.43 cw(c4850.65,2646.14) 4850.65,2621.65 ; J2.3@4877.17,2610.06 ccw(c4858.65,2601.06) 4858.65,2621.65 ccw(c4858.65,2642.25) J2.3@4877.17,2633.24 ; J2.3@4881.66,2612.25 ccw(c4866.64,2604.94) 4866.64,2621.65 ccw(c4866.64,2638.36) J2.3@4881.66,2631.06 ; J2.3@4901,2621.65 4850.65,2621.65
_L8: J2.21 RN5.5 | length 648.8
  Top Layer w5: RN5.5@4646.15,1726.01 J2.21@4896.64,1726.01 ; RN5.5@4661.76,1722.21 cw(c4670.94,1713.04) 4670.94,1726.01 cw(c4670.94,1738.99) RN5.5@4661.76,1729.81 ; 4814.43,1726.01 cw(c4814.43,1635.08) J2.21@4878.73,1699.38 ; 4826.5,1726.01 cw(c4826.5,1647.15) J2.21@4882.26,1702.92 ; 4835.47,1726.01 ccw(c4835.47,1787.18) J2.21@4878.73,1743.93 ; 4838.57,1726.01 cw(c4838.57,1659.23) J2.21@4885.8,1706.45 ; 4847.55,1726.01 ccw(c4847.55,1775.11) J2.21@4882.26,1740.39 ; 4850.64,1726.01 cw(c4850.64,1671.3) J2.21@4889.33,1709.99 ; 4859.62,1726.01 ccw(c4859.62,1763.04) J2.21@4885.8,1736.86 ; 4862.71,1726.01 cw(c4862.71,1683.37) J2.21@4892.87,1713.52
